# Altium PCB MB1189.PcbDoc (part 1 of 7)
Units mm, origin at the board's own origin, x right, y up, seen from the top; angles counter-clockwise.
Board outline 60.03 x 127.03 mm, 6 copper layers (TOP, L2_GND, L3_VCC, L4_SIG, L5_GND, BOTTOM), stack 1.58 mm thick; 273 components, 264 nets, 1114 pads, 811 vias.
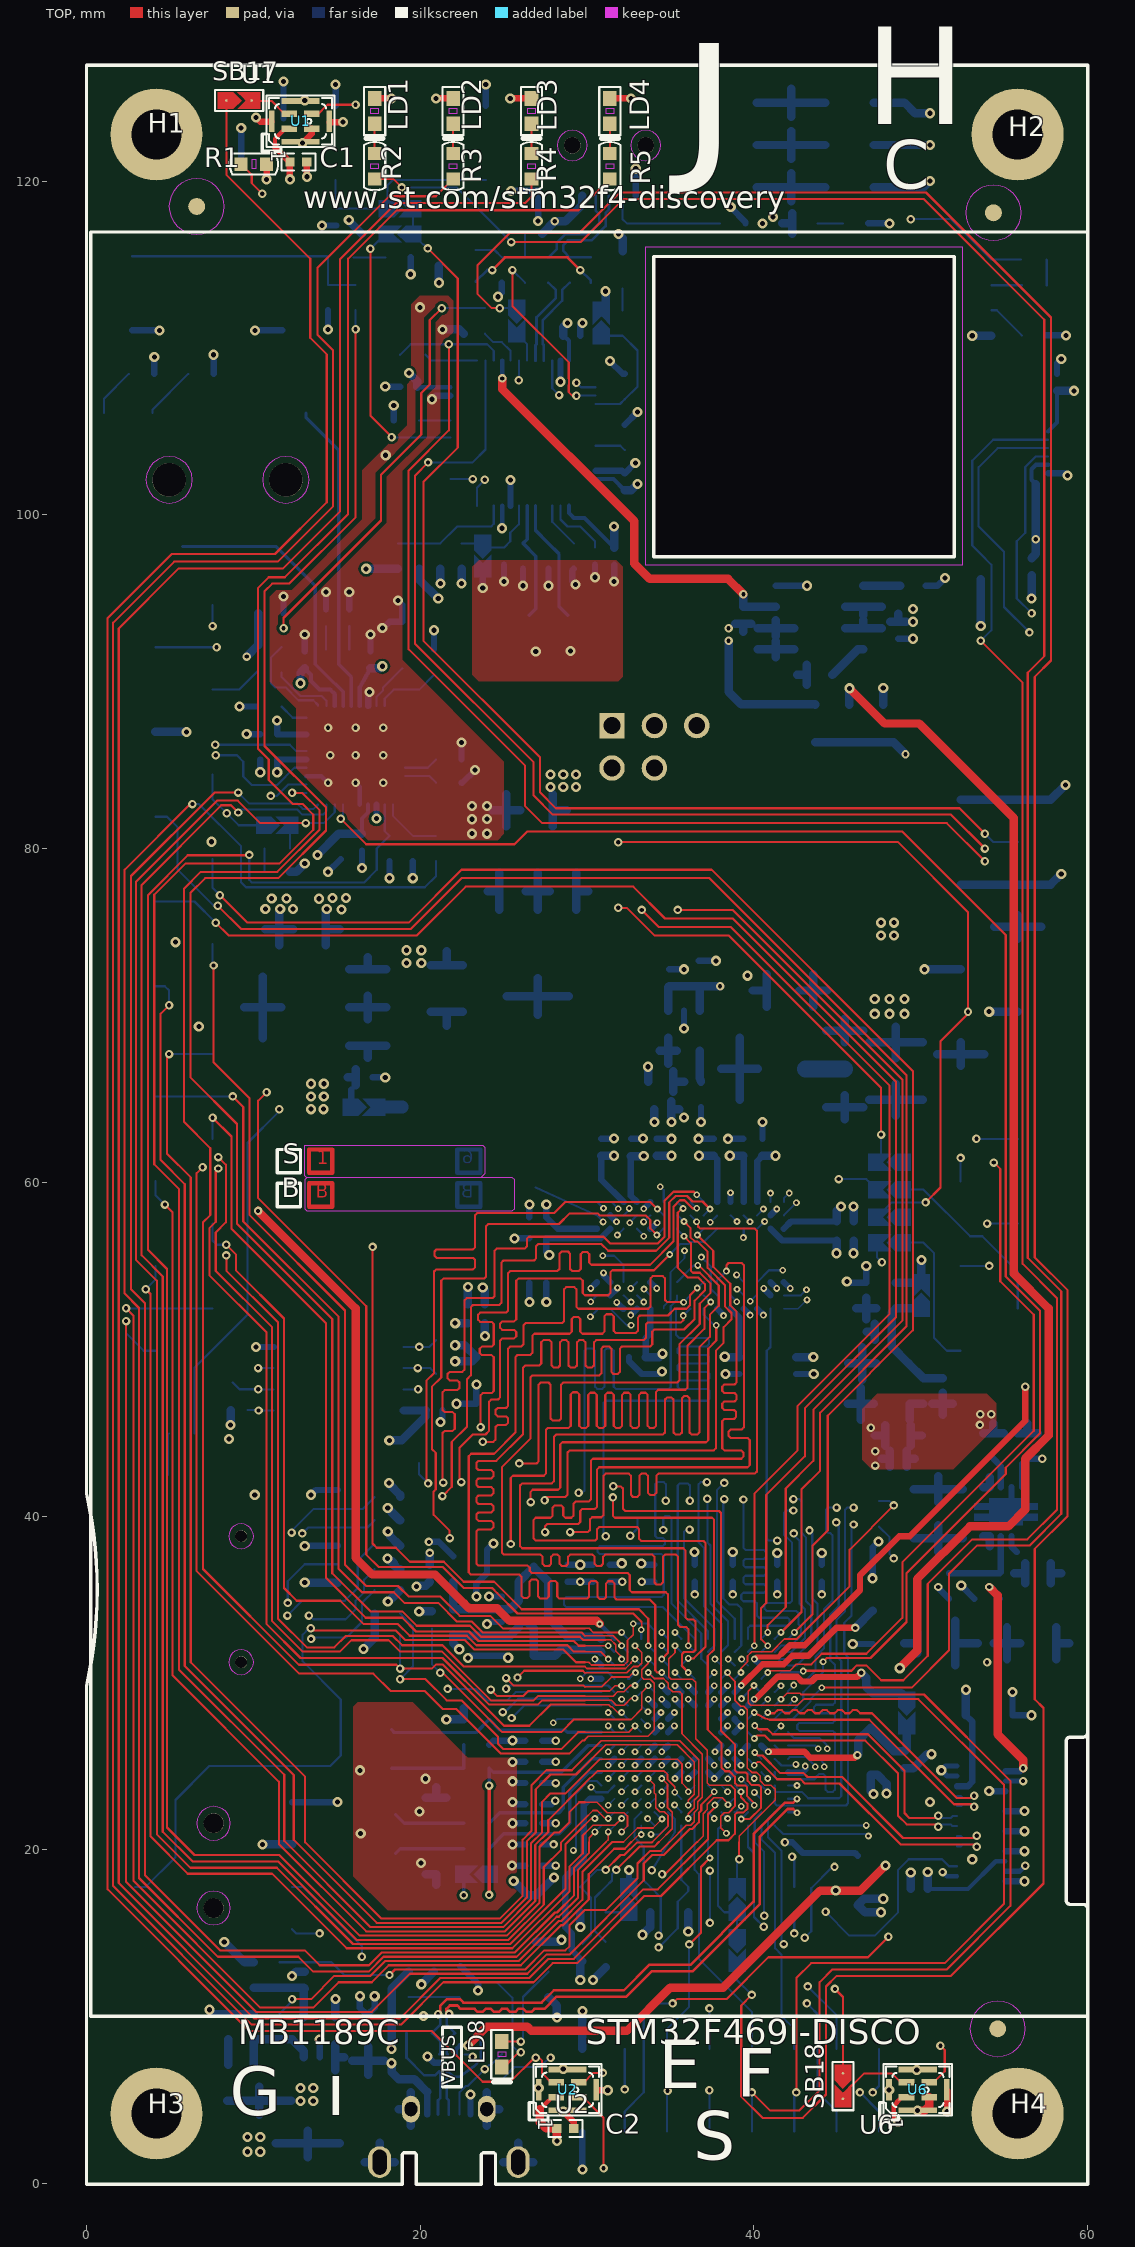
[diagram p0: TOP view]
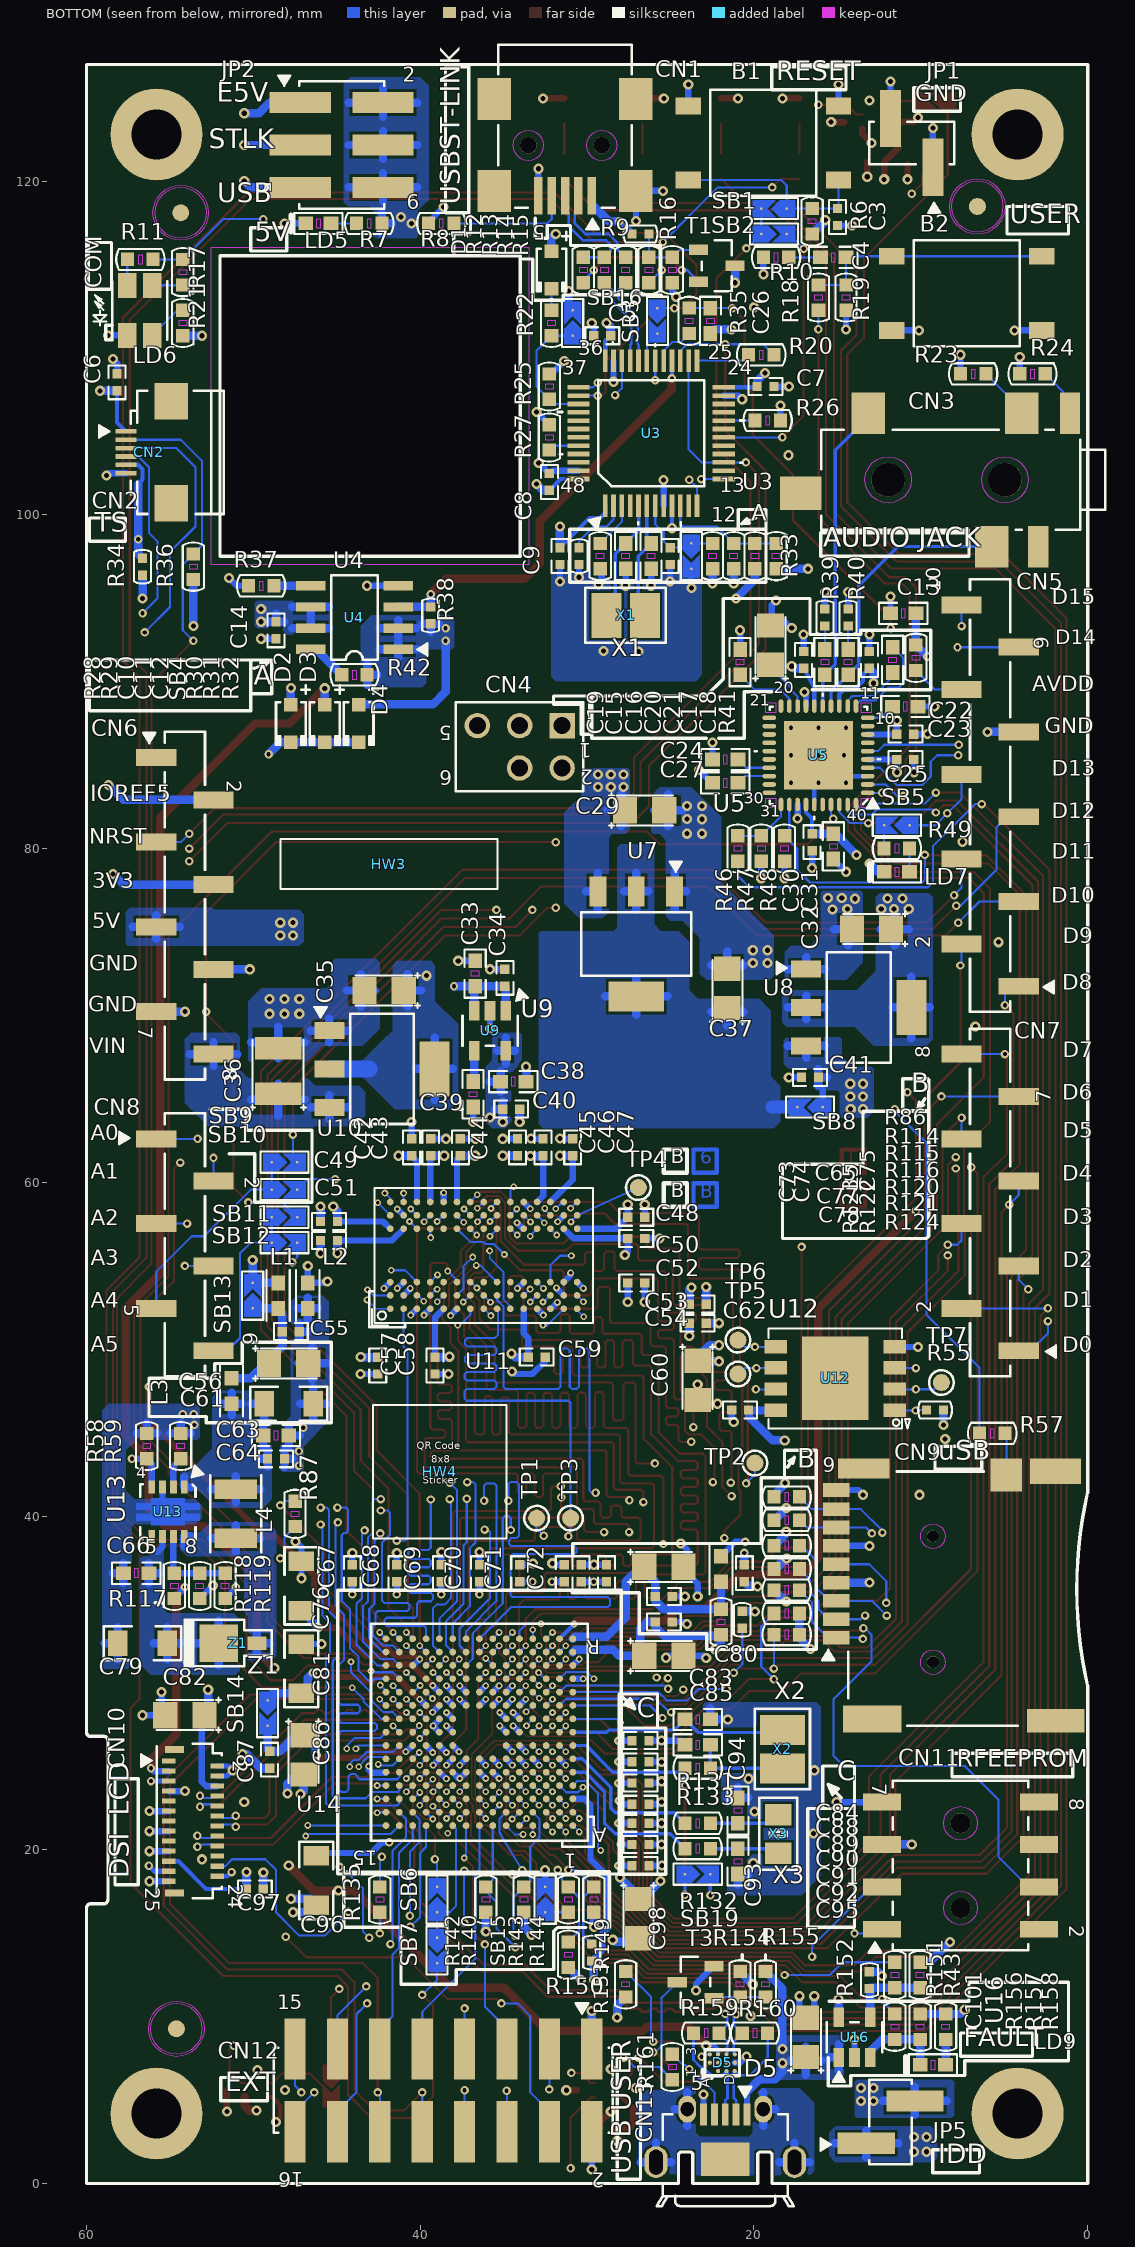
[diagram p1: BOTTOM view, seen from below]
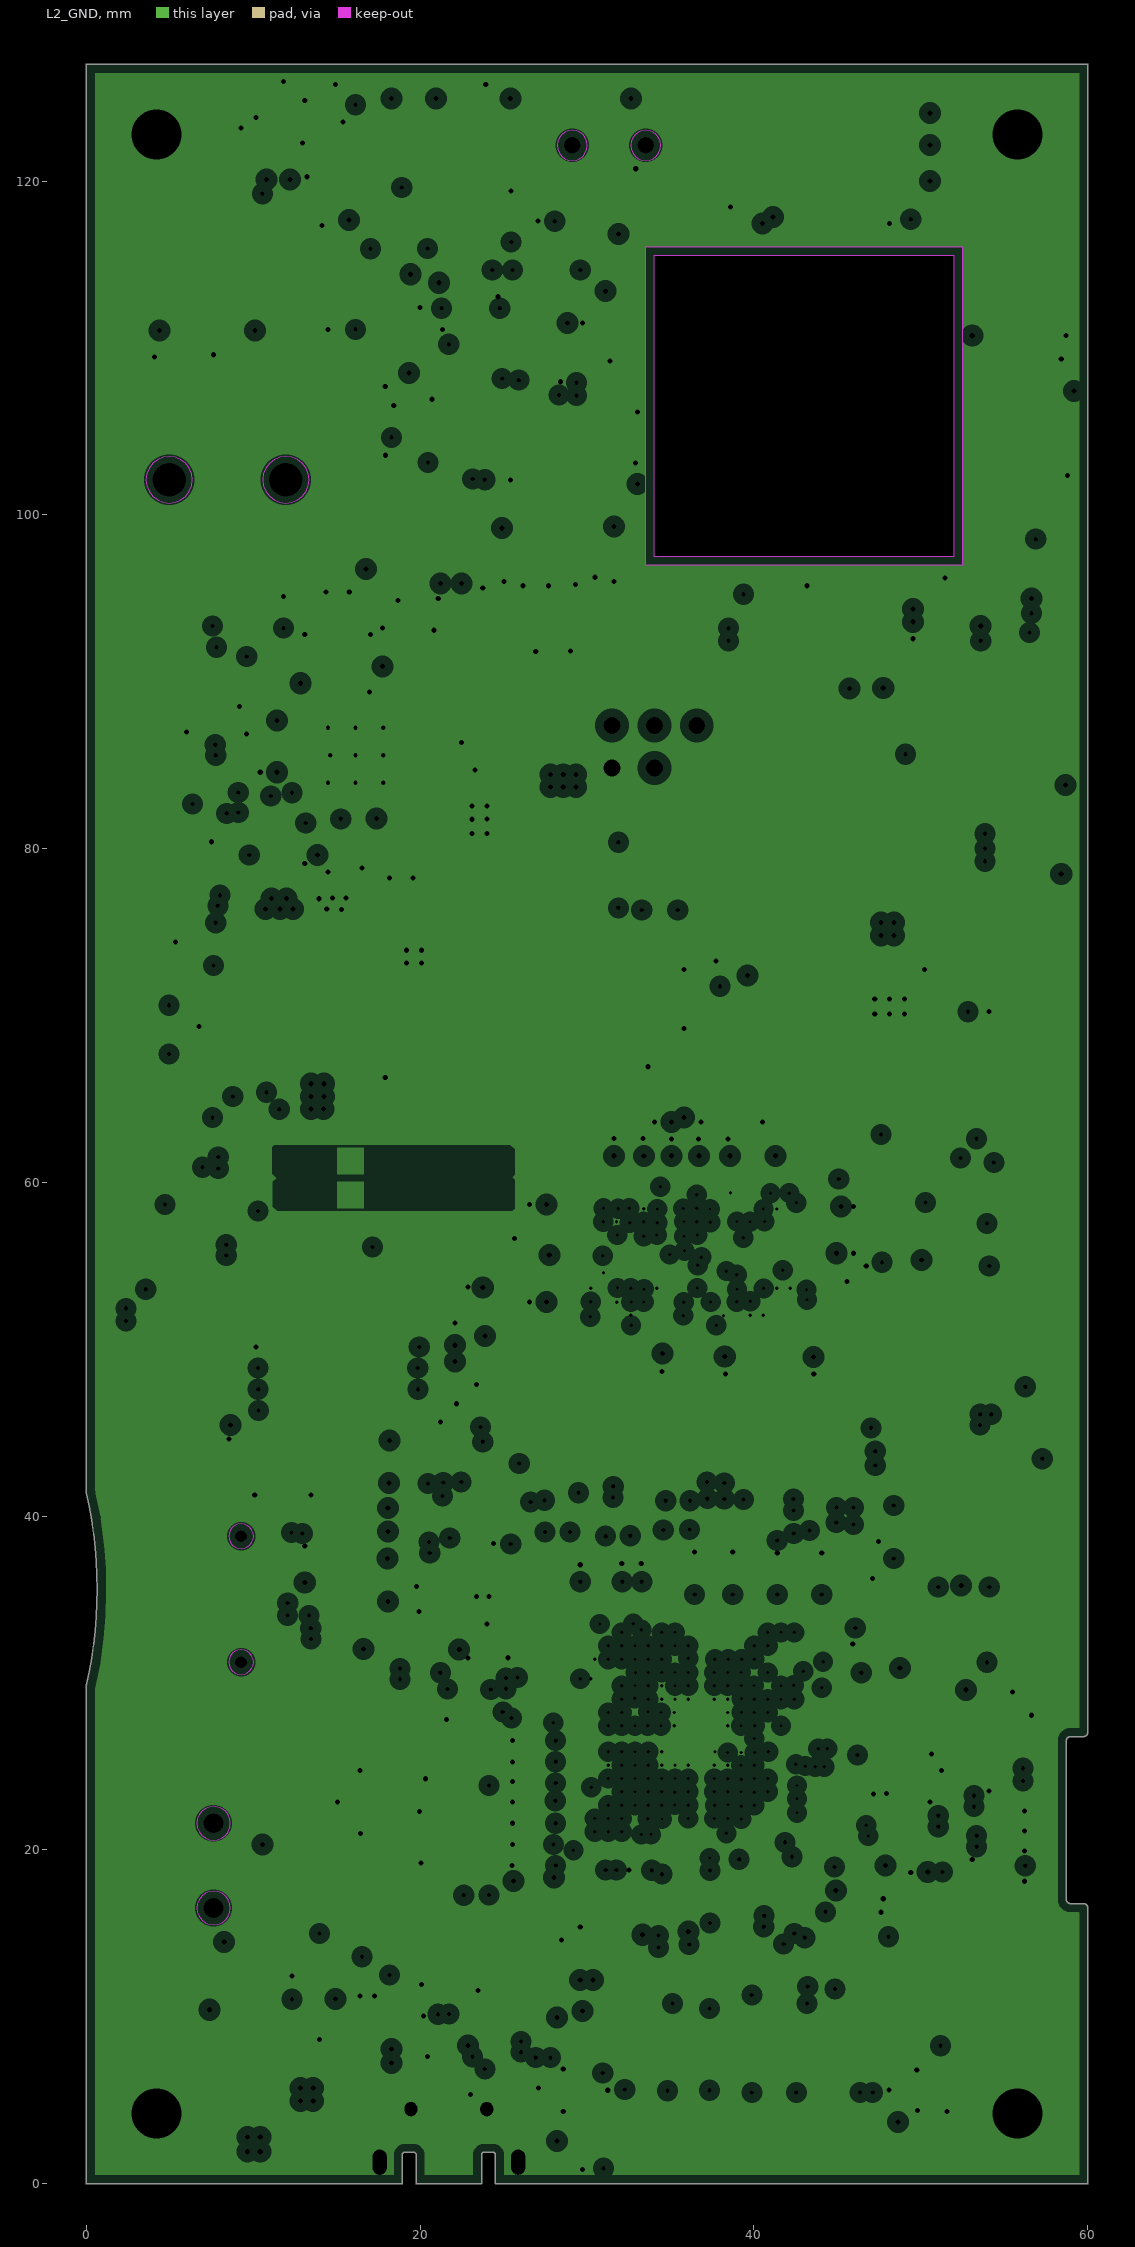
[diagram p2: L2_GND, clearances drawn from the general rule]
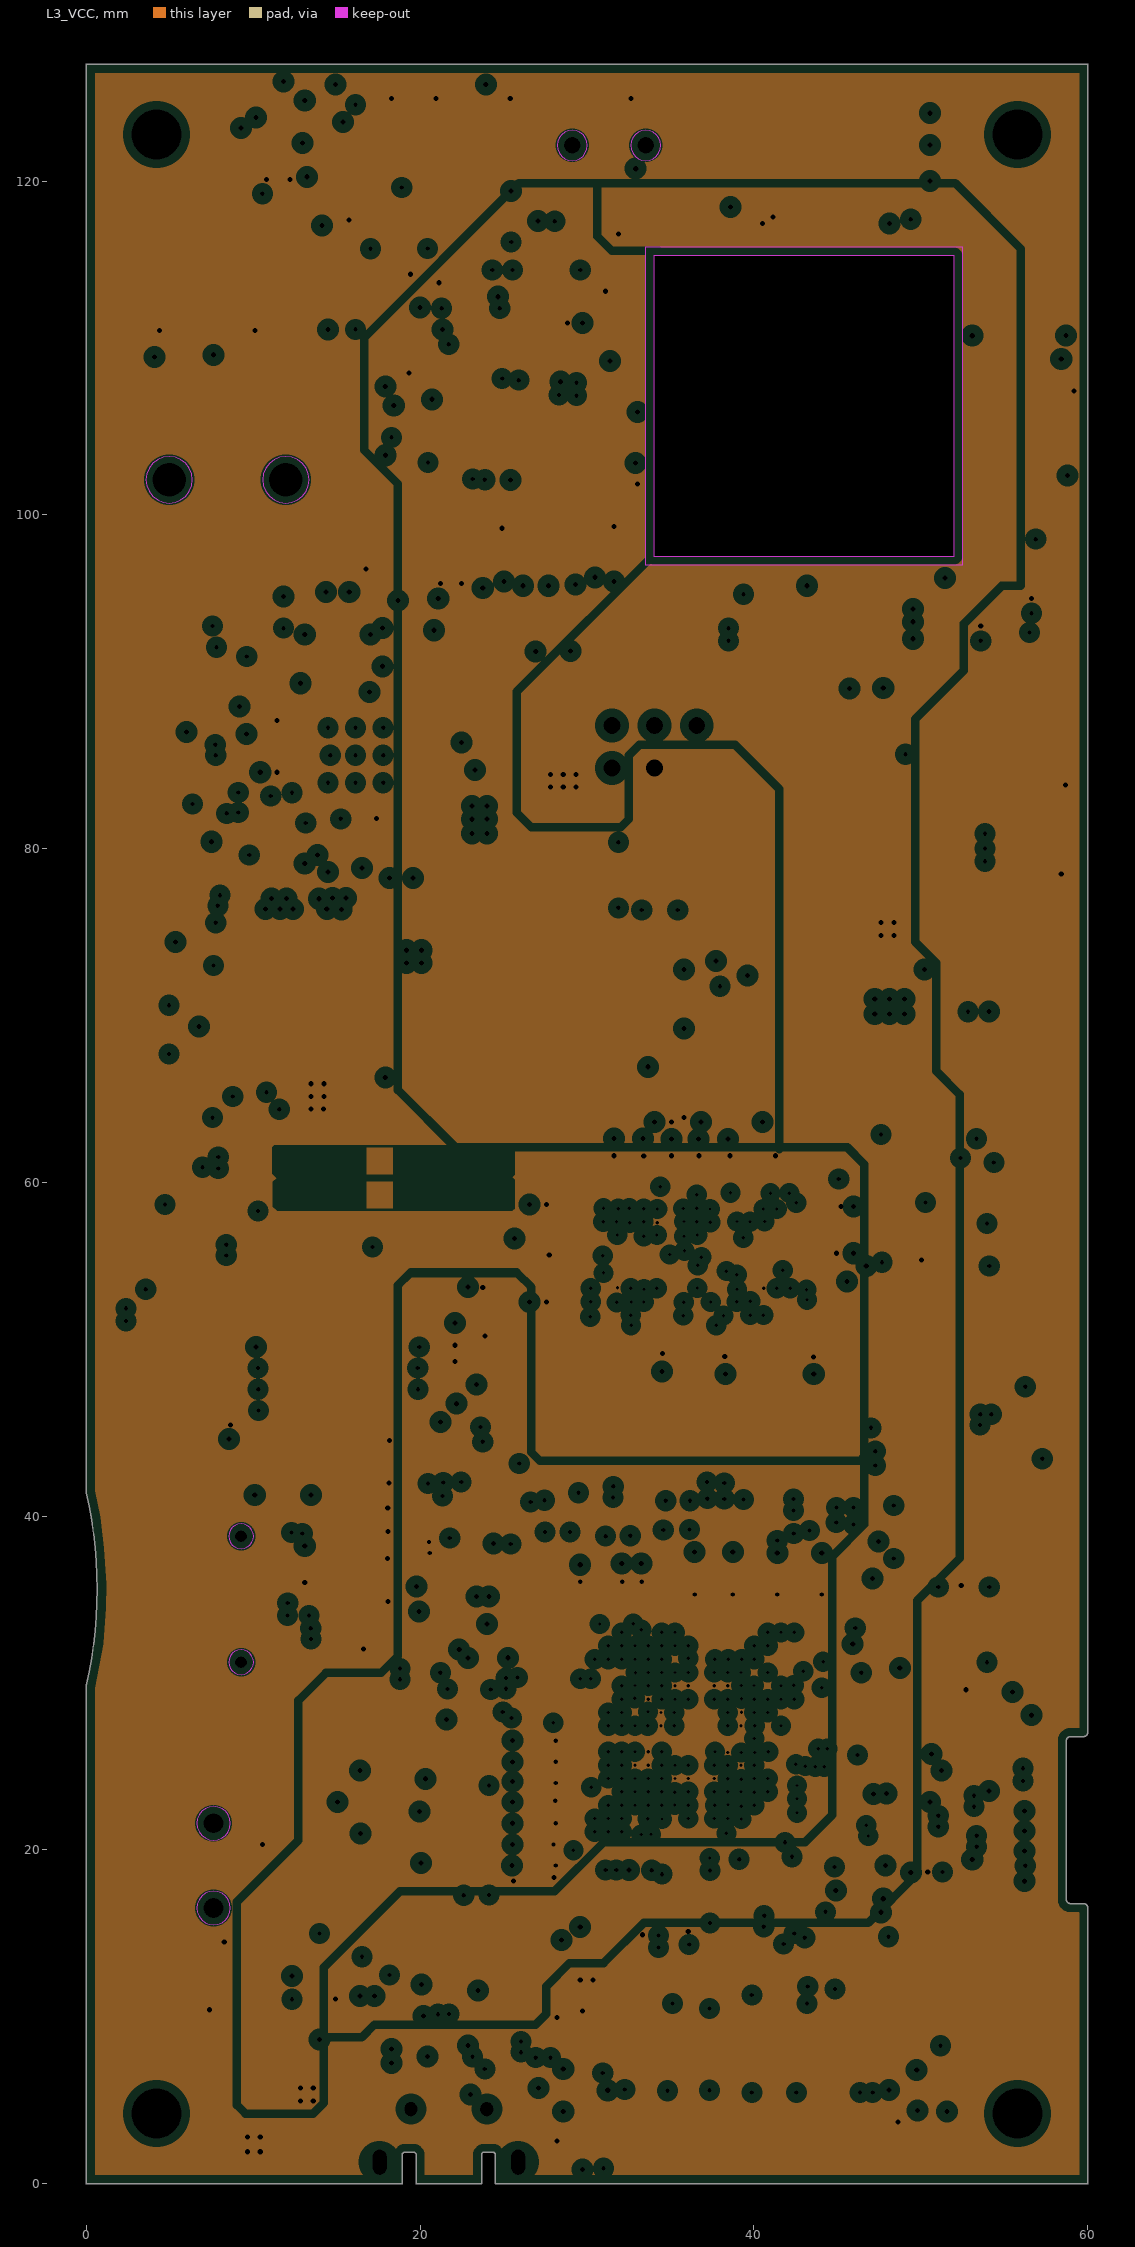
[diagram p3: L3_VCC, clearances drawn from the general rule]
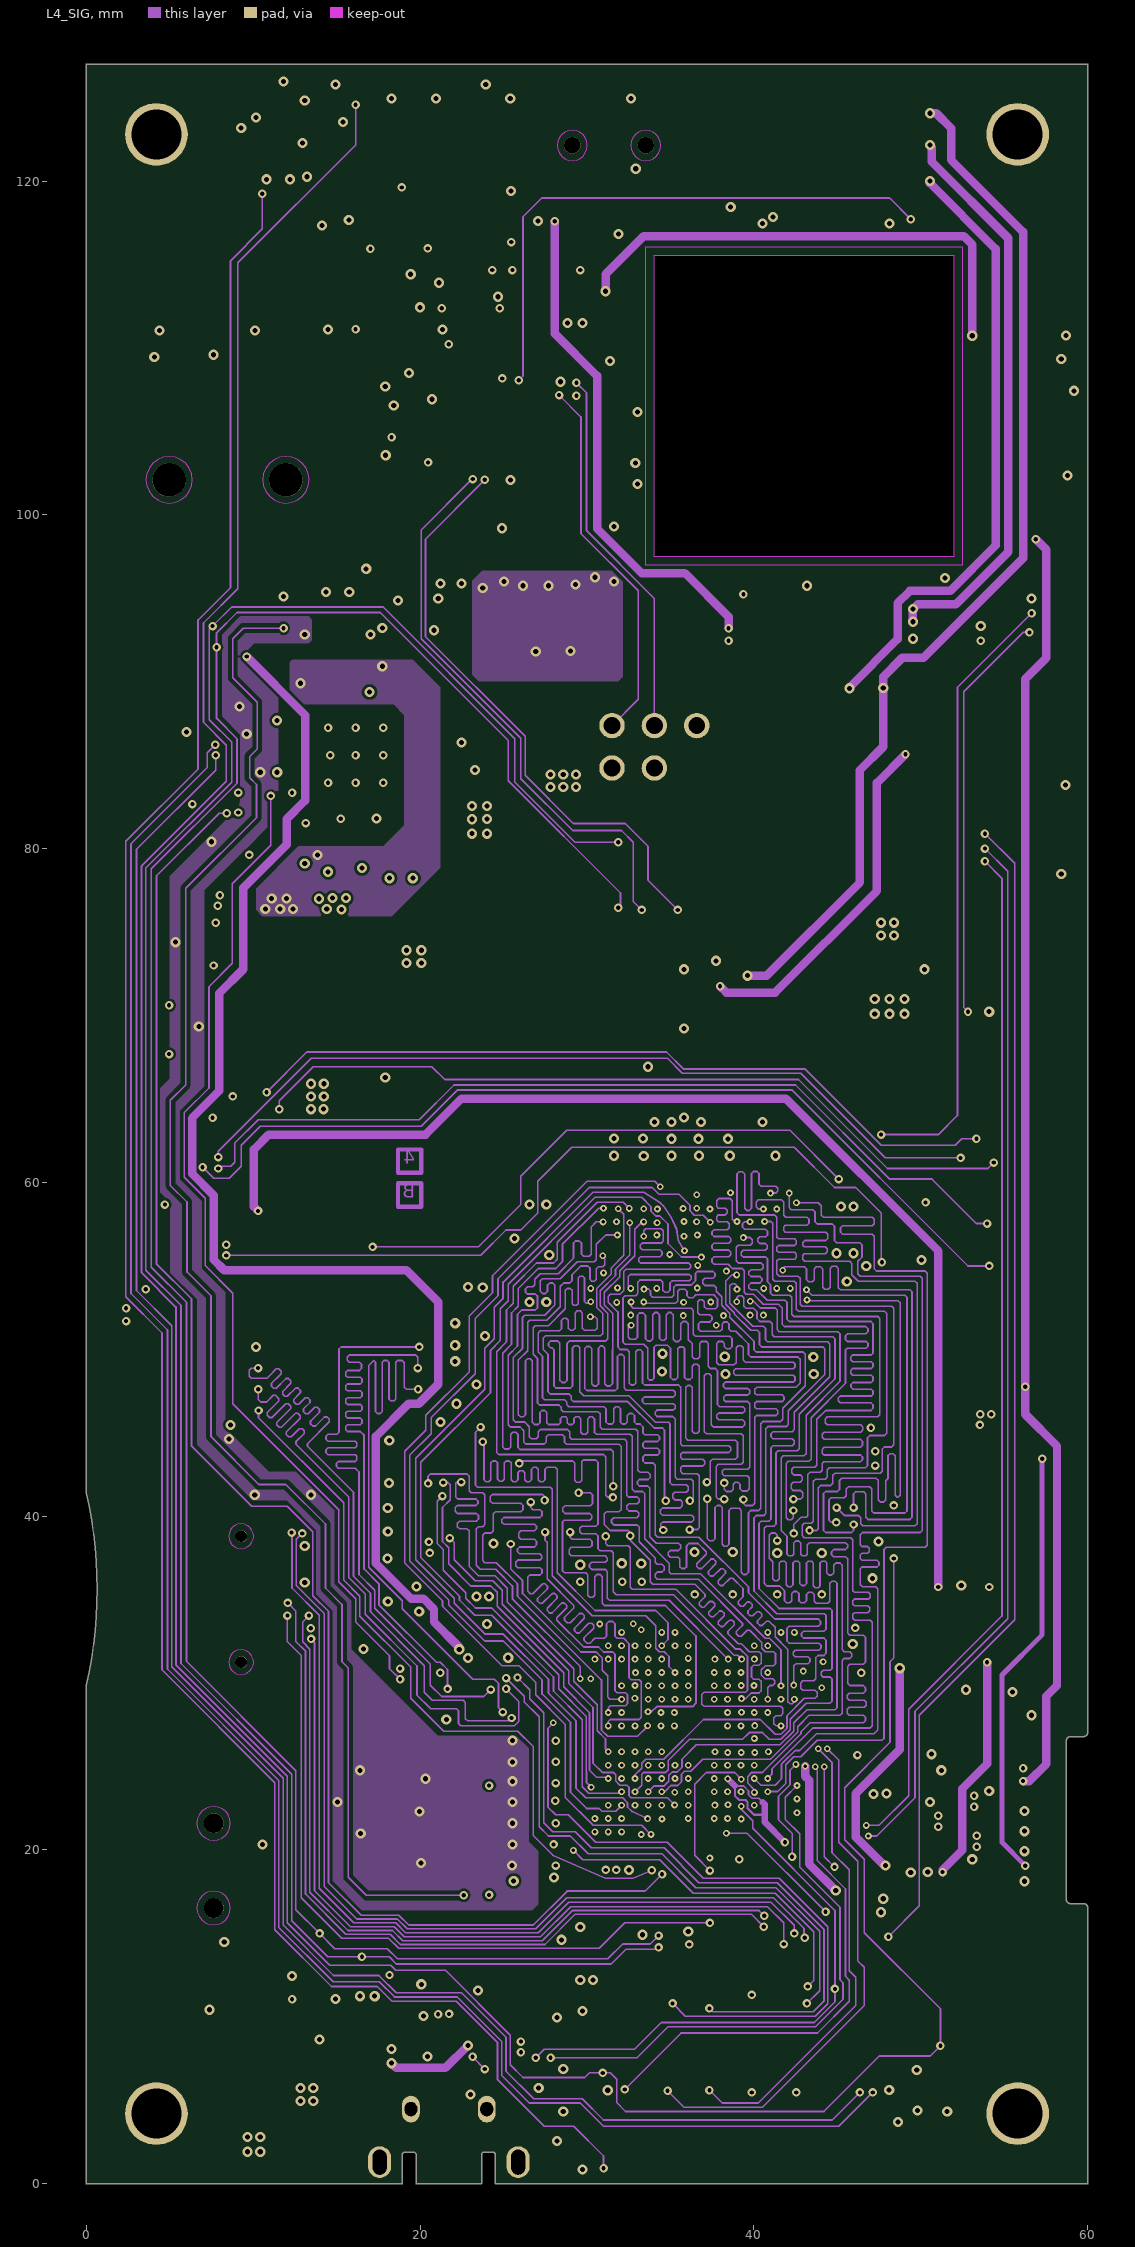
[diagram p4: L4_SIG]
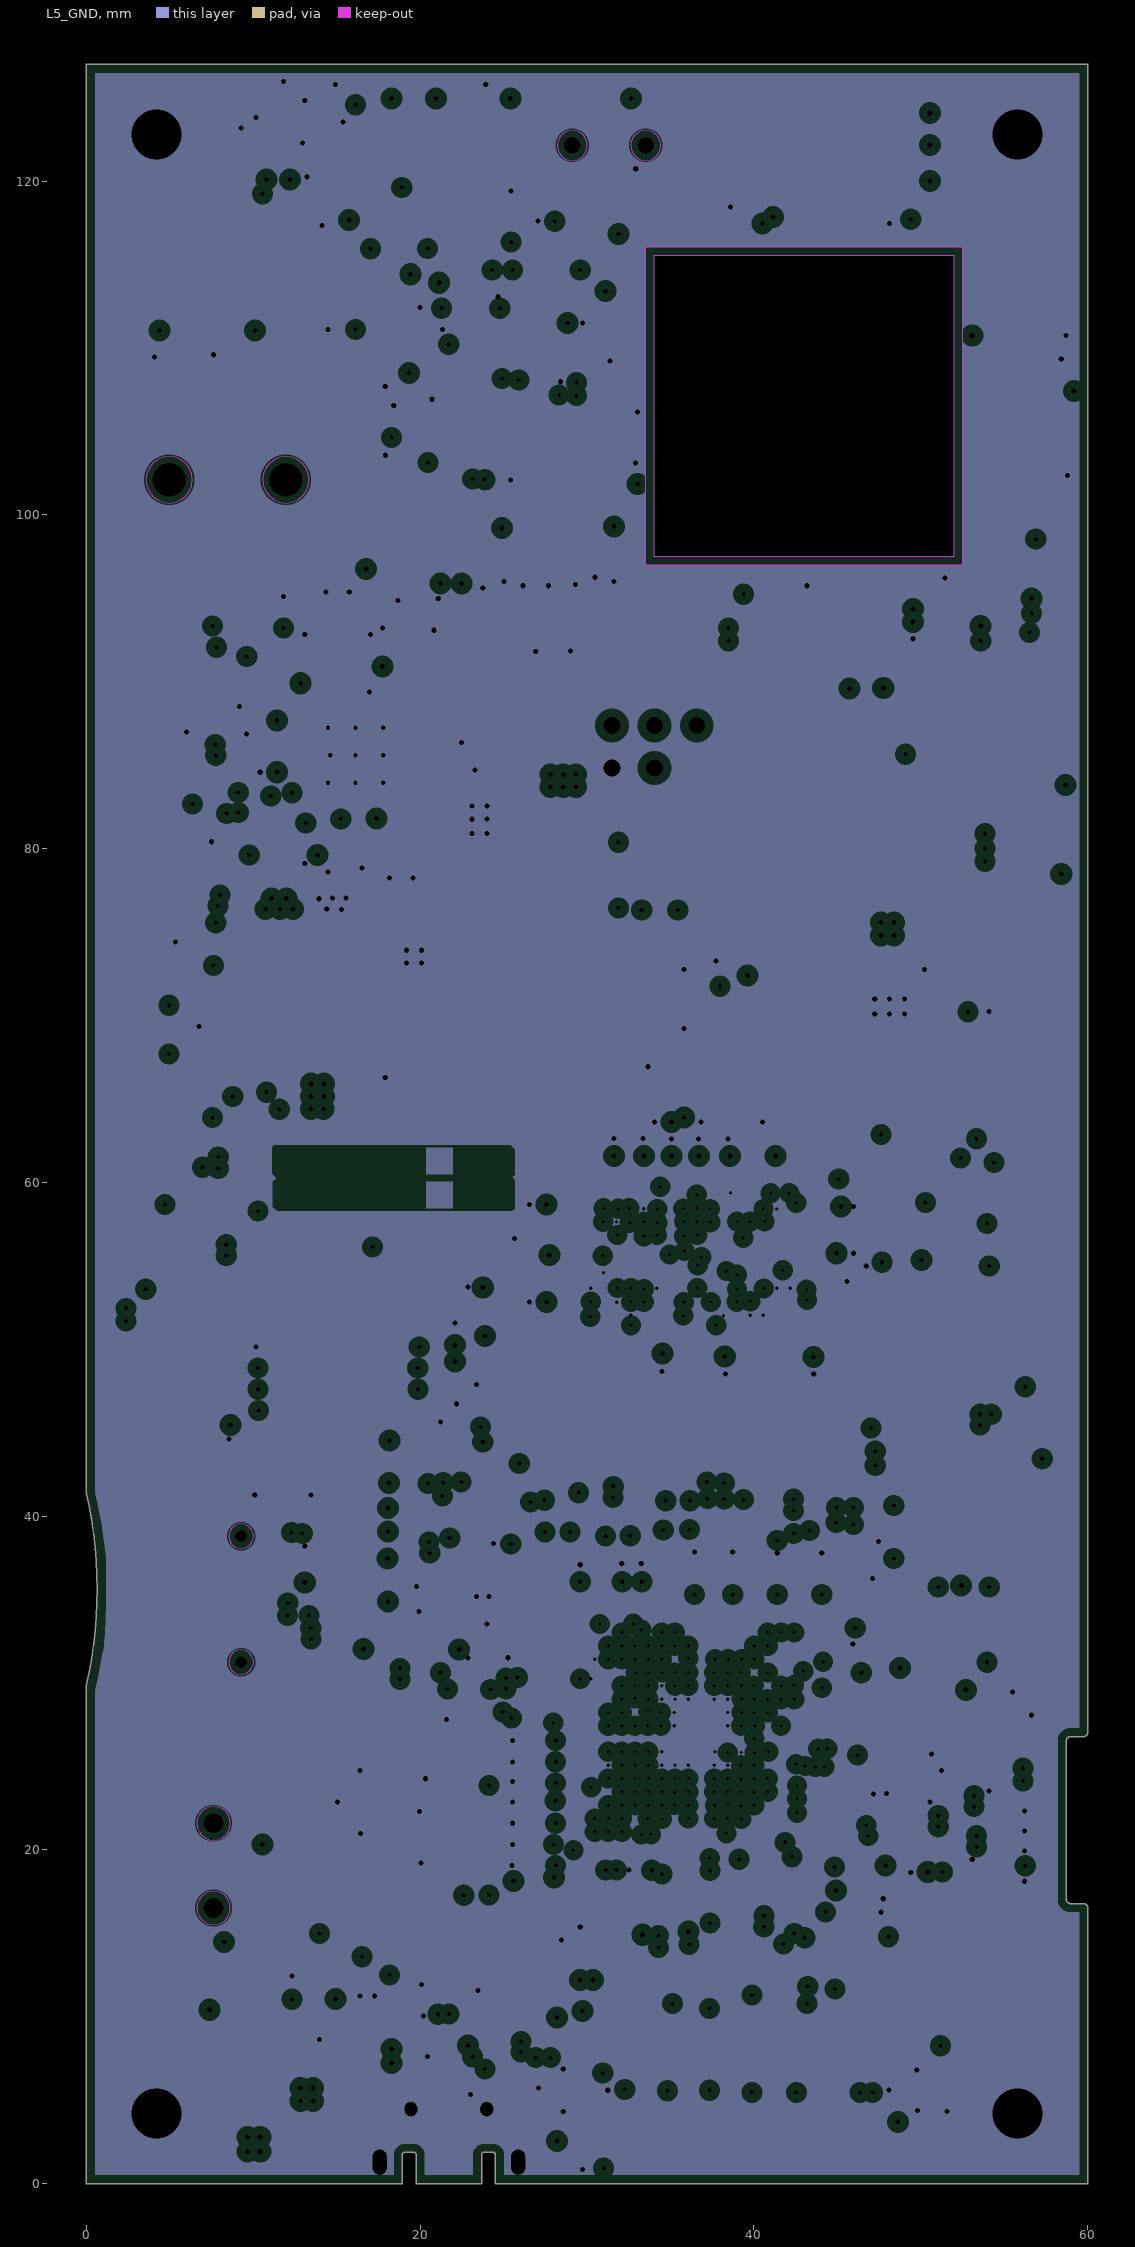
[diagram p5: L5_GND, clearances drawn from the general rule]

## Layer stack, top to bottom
Top Solder: solder mask 0.0102, Solder Resist, Dk 3.5
TOP: signal copper 0.0457
Dielectric 1: core 0.0991, FR-4, Dk 4.3
L2_GND: plane copper 0.0305, net GND
Dielectric2: core 0.1016, FR-4, Dk 4.3
L3_VCC: plane copper 0.0305, net +3V3
Dielectric3: core 0.9652, FR-4, Dk 4.3
L4_SIG: signal copper 0.0305
Dielectric4: core 0.1016, FR-4, Dk 4.3
L5_GND: plane copper 0.0305, net GND
Dielectric5: core 0.0991, FR-4, Dk 4.3
BOTTOM: signal copper 0.0457
Bottom Solder: solder mask 0.0102, Solder Resist, Dk 3.5

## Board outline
0,-0.013 cw(c0,0) -0.013,0 -0.013,29.845 cw(c0,29.845) -0.012,29.849 ccw(c-25.59,35.623) 0.631,35.623 ccw(c-25.59,35.623) -0.012,41.398 cw(c0,41.402) -0.013,41.402 -0.013,127 cw(c0,127) 0,127.013 60,127.013 cw(c60,127) 60.013,127 60.013,27.051 cw(c59.746,27.051) 59.746,26.784 58.967,26.784 ccw(c58.967,26.543) 58.726,26.543 58.726,17.018 ccw(c58.967,17.018) 58.967,16.777 59.746,16.777 cw(c59.746,16.51) 60.013,16.51 60.013,0 cw(c60,0) 60,-0.013 24.517,-0.013 cw(c24.517,0) 24.504,0 24.504,1.78 24.412,1.872 23.772,1.872 23.68,1.78 23.68,0 cw(c23.667,0) 23.667,-0.013 19.767,-0.013 cw(c19.767,0) 19.754,0 19.754,1.78 19.662,1.872 19.022,1.872 18.93,1.78 18.93,0 cw(c18.917,0) 18.917,-0.013
cut-out: 52,97.536 52,115.536 34,115.536 34,97.536

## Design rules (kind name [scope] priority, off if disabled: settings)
Clearance Clearance_Keepout [IsKeepout] p1: gap=0 ignorepadtopadclearanceinfootprint=FALSE
Clearance Clearance_STLK_MCO [(InNet('STLK_MCO') And (Layer = 'L4_SIG')) or (IsVia and Innet('PH0', 'VDD_MCU')) vs InPolygon and (Layer = 'L4_SIG')] p2: gap=0.254 ignorepadtopadclearanceinfootprint=FALSE except(0.153: Via-Fill Via-Poly Via-Region)
Clearance Clearance_BGA [TouchesRoom('RoomDefinition_U11','RoomDefinition_U14')] p3: gap=0.127 ignorepadtopadclearanceinfootprint=FALSE except(0.102: Arc-Arc Arc-Track Arc-SMDPad Arc-THPad Arc-Via Arc-Text Arc-Hole Track-Track Track-SMDPad Track-THPad Track-Via Track-Text Track-Hole SMDPad-Via SMDPad-Text SMDPad-Hole THPad-Via THPad-Text THPad-Hole Via-Text Via-Hole Text-Text Text-Hole; 0.381: Fill-Fill Fill-Poly Fill-Region Poly-Poly Poly-Region Region-Region)
Clearance Clearance_SB [HasFootprint('SB_0603') and IsRegion vs HasFootprint('SB_0603') and IsRegion] p4: gap=0.178 ignorepadtopadclearanceinfootprint=FALSE
Clearance Clearance_2W [InNetClass('A[0..15]') or InNetClass('DATA')] p5: gap=0.127 ignorepadtopadclearanceinfootprint=FALSE except(0.152: SMDPad-Fill SMDPad-Poly SMDPad-Region THPad-Fill THPad-Poly THPad-Region Via-Fill Via-Poly Via-Region Fill-Text Fill-Hole Poly-Text Poly-Hole Region-Text Region-Hole; 0.254: Arc-Fill Arc-Poly Arc-Region Track-Fill Track-Poly Track-Region; 0.508: Fill-Fill Fill-Poly Fill-Region Poly-Poly Poly-Region Region-Region)
Clearance [All] p6: gap=0.127 ignorepadtopadclearanceinfootprint=FALSE except(0.152: Arc-Fill Arc-Poly Arc-Region Track-Fill Track-Poly Track-Region SMDPad-Fill SMDPad-Poly SMDPad-Region THPad-Fill THPad-Poly THPad-Region Via-Fill Via-Poly Via-Region Fill-Text Fill-Hole Poly-Text Poly-Hole Region-Text Region-Hole; 0.508: Fill-Fill Fill-Poly Fill-Region Poly-Poly Poly-Region Region-Region)
DiffPairsRouting DiffPairsRouting_100Ohm [InDifferentialPair('HSSI_CLK', 'HSSI_D0', 'HSSI_D1')] p1: maxlimit=0.279 minlimit=0.102 mostfreqgap=0.277 toplayer_maxgap=0.254 toplayer_prefgap=0.252 toplayer_minwidth=0.127 toplayer_maxwidth=0.254 toplayer_prefwidth=0.129 midlayer1_minwidth=0.102 midlayer1_maxwidth=0.279 midlayer1_prefwidth=0.104 bottomlayer_maxgap=0.254 bottomlayer_prefgap=0.252 bottomlayer_minwidth=0.127 bottomlayer_maxwidth=0.254 bottomlayer_prefwidth=0.129 maxuncoupledlength=12.7
DiffPairsRouting DiffPairsRouting_90Ohm [InDifferentialPair('USB_FS1', 'MICROAB')] p2: maxlimit=0.254 minlimit=0.102 mostfreqgap=0.252 toplayer_maxgap=0.229 toplayer_prefgap=0.226 toplayer_minwidth=0.102 toplayer_maxwidth=0.155 toplayer_prefwidth=0.155 midlayer1_minwidth=0.102 midlayer1_maxwidth=0.13 midlayer1_prefwidth=0.13 bottomlayer_maxgap=0.229 bottomlayer_prefgap=0.226 bottomlayer_minwidth=0.102 bottomlayer_maxwidth=0.155 bottomlayer_prefwidth=0.155 maxuncoupledlength=12.7
HoleSize [All] p1: absolutevalues=TRUE maxlimit=3.048 minlimit=0.025 maxpercent=80.000 minpercent=20.000
MatchedLengths "Schematic Matched Net Lengths_20" [InNetClass('A[0..15]')] p1: tolerance=6.35 checknetsindiffpair=FALSE checkdiffpairvsdiffpair=TRUE checkxsignals=TRUE checkothers=TRUE
MatchedLengths "Schematic Matched Net Lengths_19" [InNet('PC0')] p2: tolerance=6.35 checknetsindiffpair=FALSE checkdiffpairvsdiffpair=TRUE checkxsignals=TRUE checkothers=TRUE
MatchedLengths "Schematic Matched Net Lengths_18" [InNetClass('D[0..31]')] p3: tolerance=6.35 checknetsindiffpair=FALSE checkdiffpairvsdiffpair=TRUE checkxsignals=TRUE checkothers=TRUE
MatchedLengths "Schematic Matched Net Lengths_16" [InNetClass('A[0..11]')] p4: tolerance=6.35 checknetsindiffpair=FALSE checkdiffpairvsdiffpair=TRUE checkxsignals=TRUE checkothers=TRUE
MatchedLengths "Schematic Matched Net Lengths_15" [InNet('PG8')] p5: tolerance=6.35 checknetsindiffpair=FALSE checkdiffpairvsdiffpair=TRUE checkxsignals=TRUE checkothers=TRUE
MatchedLengths "Schematic Matched Net Lengths_14" [InNet('PG15')] p6: tolerance=6.35 checknetsindiffpair=FALSE checkdiffpairvsdiffpair=TRUE checkxsignals=TRUE checkothers=TRUE
MatchedLengths "Schematic Matched Net Lengths_13" [InNet('PH3')] p7: tolerance=6.35 checknetsindiffpair=FALSE checkdiffpairvsdiffpair=TRUE checkxsignals=TRUE checkothers=TRUE
MatchedLengths "Schematic Matched Net Lengths_12" [InNet('PF11')] p8: tolerance=6.35 checknetsindiffpair=FALSE checkdiffpairvsdiffpair=TRUE checkxsignals=TRUE checkothers=TRUE
MatchedLengths "Schematic Matched Net Lengths_11" [InNet('HSSI_CLK_N')] p9: tolerance=2.54 checknetsindiffpair=TRUE checkdiffpairvsdiffpair=FALSE checkxsignals=FALSE checkothers=FALSE
MatchedLengths "Schematic Matched Net Lengths_10" [InNet('HSSI_CLK_P')] p10: tolerance=2.54 checknetsindiffpair=TRUE checkdiffpairvsdiffpair=FALSE checkxsignals=FALSE checkothers=FALSE
MatchedLengths "Schematic Matched Net Lengths_9" [InNet('HSSI_D0_N')] p11: tolerance=2.54 checknetsindiffpair=TRUE checkdiffpairvsdiffpair=FALSE checkxsignals=FALSE checkothers=FALSE
MatchedLengths "Schematic Matched Net Lengths_8" [InNet('HSSI_D0_P')] p12: tolerance=2.54 checknetsindiffpair=TRUE checkdiffpairvsdiffpair=FALSE checkxsignals=FALSE checkothers=FALSE
MatchedLengths "Schematic Matched Net Lengths_7" [InNet('HSSI_D1_N')] p13: tolerance=2.54 checknetsindiffpair=TRUE checkdiffpairvsdiffpair=FALSE checkxsignals=FALSE checkothers=FALSE
MatchedLengths "Schematic Matched Net Lengths_6" [InNet('PF8')] p14: tolerance=2.54 checknetsindiffpair=FALSE checkdiffpairvsdiffpair=TRUE checkxsignals=TRUE checkothers=TRUE
MatchedLengths "Schematic Matched Net Lengths_5" [InNet('PF9')] p15: tolerance=2.54 checknetsindiffpair=FALSE checkdiffpairvsdiffpair=TRUE checkxsignals=TRUE checkothers=TRUE
MatchedLengths "Schematic Matched Net Lengths_4" [InNet('PF7')] p16: tolerance=2.54 checknetsindiffpair=FALSE checkdiffpairvsdiffpair=TRUE checkxsignals=TRUE checkothers=TRUE
MatchedLengths "Schematic Matched Net Lengths_3" [InNet('PF6')] p17: tolerance=2.54 checknetsindiffpair=FALSE checkdiffpairvsdiffpair=TRUE checkxsignals=TRUE checkothers=TRUE
MatchedLengths "Schematic Matched Net Lengths_2" [InNet('PB6')] p18: tolerance=2.54 checknetsindiffpair=FALSE checkdiffpairvsdiffpair=TRUE checkxsignals=TRUE checkothers=TRUE
MatchedLengths "Schematic Matched Net Lengths_1" [InNet('PF10')] p19: tolerance=2.54 checknetsindiffpair=FALSE checkdiffpairvsdiffpair=TRUE checkxsignals=TRUE checkothers=TRUE
MatchedLengths "Schematic Matched Net Lengths" [InNet('HSSI_D1_P')] p20: tolerance=2.54 checknetsindiffpair=TRUE checkdiffpairvsdiffpair=FALSE checkxsignals=FALSE checkothers=FALSE
PlaneClearance PlaneClearance_Fixations [HasFootprint('HOLE_C5R5D3')] p1: clearance=0.381
PlaneClearance "PlaneClearance_Via 16mil" [(ObjectKind = 'Via') And (AsMils(PadXSize_TopLayer) = 16) And (AsMils(PadXSize_MidLayer1) = 16) And (AsMils(PadXSize_BottomLayer) = 16)] p2: clearance=0.229
PlaneClearance PlaneClearance_CN4 [InComponent('CN4')] p3: clearance=0.381
PlaneClearance PlaneClearance_NonPlatedPads [(PadIsPlated = 'False')] p4: clearance=0.406
PlaneClearance PlaneClearance_Via [IsVia] p5: clearance=0.254
PlaneClearance [All] p6: clearance=0.508
PlaneConnect PlaneConnect_Fixations [HasFootprint('HOLE_C5R5D3')] p1: planeconnectstyle=Relief reliefexpansion=0.203 reliefentries=4 reliefconductorwidth=0.762 reliefairgap=0.178
PlaneConnect [All] p2: pad.planeconnectstyle=Relief pad.reliefexpansion=0.203 pad.reliefentries=4 pad.reliefconductorwidth=0.381 pad.reliefairgap=0.178 via.planeconnectstyle=Direct via.reliefexpansion=0.508 via.reliefentries=4 via.reliefconductorwidth=0.254 via.reliefairgap=0.254
PolygonConnect PolygonConnect_CN13 [IsPad and (Name = 'CN13-10')] p1: connectstyle=Direct reliefconductorwidth=0.254 reliefentries=4 polygonreliefangle="90 Angle" airgapwidth=0.254
PolygonConnect [All] p2: thpad.connectstyle=Relief thpad.reliefconductorwidth=0.254 thpad.reliefentries=4 thpad.polygonreliefangle="90 Angle" thpad.airgapwidth=0.152 smdpad.connectstyle=Relief smdpad.reliefconductorwidth=0.254 smdpad.reliefentries=4 smdpad.polygonreliefangle="90 Angle" smdpad.airgapwidth=0.152 via.connectstyle=Direct via.reliefconductorwidth=0.254 via.reliefentries=4 via.polygonreliefangle="90 Angle" via.airgapwidth=0.254
RoomDefinition RoomDefinition_U11 [False] p1: confinementstyle=ConfineIn formatcopy=TRUE lockcomponents=FALSE outline 29.21,59.95 43.155,59.95 43.155,51.13 29.21,51.13
RoomDefinition RoomDefinition_U14 [False] p2: confinementstyle=ConfineIn formatcopy=TRUE lockcomponents=FALSE outline 29.87,33.63 43.028,33.63 43.028,20.472 29.87,20.472
RoutingVias [All] p1: holewidth=0.3 width=0.6 viastyle="Through Hole" minholewidth=0.2 minwidth=0.25 maxholewidth=0.5 maxwidth=0.65
SolderMaskExpansion SolderMaskExpansion_1 [IsVia] p1: expansion=0.076 istentingtop=FALSE soldermaskfromhole=TRUE
SolderMaskExpansion [All] p2: expansion=0.076 istentingtop=FALSE
Width Width_BGA [TouchesRoom('RoomDefinition_U11','RoomDefinition_U14')] p1: maxlimit=1.016 minlimit=0.102 preferedwidth=0.102
Width Width_20mil [InNet('GND', 'E5V', '+1V8', '+3V3', 'VDD_MCU', 'U5V_ST_LINK')] p2: maxlimit=2.032 minlimit=0.127 preferedwidth=0.508
Width [All] p3: maxlimit=1.016 minlimit=0.102 preferedwidth=0.127 toplayer_minwidth=0.127 midlayer1_prefwidth=0.102 bottomlayer_minwidth=0.127 minimp=2.670000 maximp=36.460000 favimp=1.510000
26 further rules are at their usual default settings.

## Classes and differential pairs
net class D[0..31]: D0 D1 D2 D3 D4 D5 D6 D7 D8 D9 D10 D11 D12 D13 D14 D15 D16 D17 D18 D19 D20 D21 D22 D23 D24 D25 D26 D27 D28 D29 D30 D31
net class A[0..15]: A0 A1 A2 A3 A4 A5 A6 A7 A8 A9 A10 A11 A14 A15
component class U_USB_OTG_FS: C101 CN13 D5 LD8 LD9 R43 R151 R152 R153 R154 R155 R156 R157 R158 R159 R160 R161 T3 U16
component class U_ST_LINK_V2-1: C5 C7 C8 C9 C10 C11 C12 C14 C26 C33 C34 C38 C39 C40 CN1 CN4 D1 D2 D3 D4 LD6 R8 R9 R11 R12 R13 R14 R15 R16 R17 R20 R21 R22 R25 R26 R27 R28 R29 R30 R31 R32 R33 R35 R37 R38 R42 SB2 SB3 SB4 SB16 T1 U3 U4 U9 X1
component class U_QSPI: C62 R55 TP5 TP6 TP7 U12
component class U_Power: C29 C32 C35 C36 C37 C41 JP1 JP2 JP5 LD5 R7 SB8 U7 U8 U10
component class U_Peripherals: B1 B2 C3 C4 CN9 CN11 LD1 LD2 LD3 LD4 R2 R3 R4 R5 R6 R10 R18 R19 R57 R86 R114 R115 R116 R120 SB1
component class U_Memory: C42 C43 C44 C45 C46 C47 C48 C49 C50 C51 C52 C57 C58 C59 TP2 TP3 TP4 U11
component class U_MCU: C53 C54 C60 C65 C67 C68 C69 C70 C71 C72 C73 C74 C75 C76 C77 C78 C80 C81 C83 C84 C85 C86 C87 C88 C89 C90 C91 C92 C93 C94 C95 C96 C98 L5 R87 R121 R122 R123 R124 R131 R132 R133 R135 R140 R142 R143 R144 R149 R150 SB6 SB7 SB14 SB15 SB19 TP1 U14 X2 X3
component class U_ExtensionConnector: CN12
component class U_DSI_LCD: C6 C55 C56 C61 C63 C64 C66 C79 C82 C97 CN2 CN10 L1 L2 L3 L4 R34 R36 R58 R59 R117 R118 R119 SB13 U13 Z1 ZZ1
component class U_AUDIO2: C1 C2 C15 C16 C17 C18 C19 C20 C21 C22 C23 C24 C25 C27 C30 C31 CN3 R1 R23 R24 R39 R40 R46 R47 R48 SB17 SB18 U1 U2 U5 U6
component class "U_Arduino_ Connectors": C13 CN5 CN6 CN7 CN8 LD7 R41 R49 SB5 SB9 SB10 SB11 SB12
component class U_Top: H1 H2 H3 H4 HW3 HW4 ZZ2 ZZ3 ZZ4 ZZ5 ZZ6 ZZ7 ZZ8 ZZ9
differential pair USB_FS1: +USB_FS1_P -USB_FS1_N
differential pair MICROAB: +MICROAB_P -MICROAB_N
differential pair HSSI_D1: +HSSI_D1_P -HSSI_D1_N
differential pair HSSI_D0: +HSSI_D0_P -HSSI_D0_N
differential pair HSSI_CLK: +HSSI_CLK_P -HSSI_CLK_N

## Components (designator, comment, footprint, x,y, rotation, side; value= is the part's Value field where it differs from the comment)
B1 "CTSM-644N-V-T/R" PB10 19.431,122.301 r0 bottom
B2 "CTSM-644B-V-T/R" PB10 7.239,113.284 r0 bottom
C1 "100nF" 0402C#1 12.7,121.158 r180 top
C2 "100nF" 0402C#1 28.702,3.302 r180 top
C3 "100nF" 0402C#1 14.986,117.856 r90 bottom value=100NF
C4 "[N/A]" 0603C#1 15.24,115.443 r0 bottom value=100pF
C5 "100nF" 0402C#2 29.083,110.744 r0 bottom
C6 "100nF" 0402C#1 58.166,107.95 r270 bottom
C7 "100nF" 0402C#1 19.304,107.696 r0 bottom
C8 "100nF" 0402C#1 32.258,101.981 r270 bottom
C9 "100nF" 0402C#1 31.623,97.536 r90 bottom
C10 "10pF" 0603C#2 27.686,97.536 r270 bottom
C11 "10pF" 0603C#2 26.162,97.536 r270 bottom
C12 "100nF" 0402C#1 25.019,97.536 r90 bottom
C13 "[N/A]" 0603C#1 11.049,94.107 r0 bottom value=10nF
C14 "100nF" 0402C#1 48.641,93.091 r90 bottom
C15 "10uF" CPOL_TAJ-A_1206_H180 19,92.2 r90 bottom value="10uF (16V)"
C16 "100nF" 0402C#1 17.018,91.313 r90 bottom
C17 "100nF" 0402C#1 13.081,91.313 r90 bottom value=100NF
C18 "1uF" 0603C#2 11.684,91.313 r270 bottom
C19 "1uF" 0603C#2 20.828,91.186 r270 bottom
C20 "22nF" 0603C#2 15.748,91.186 r90 bottom
C21 "22nF" 0603C#2 14.351,91.186 r90 bottom
C22 "1uF" 0603C#2 10.922,88.519 r0 bottom
C23 "100nF" 0402C#1 10.922,86.868 r0 bottom
C24 "150pF_NPO_5%_0603" 0603C#1 21.717,85.344 r0 bottom value=150pF
C25 "100nF" 0402C#2 10.922,85.344 r0 bottom
C26 "20pF" 0603C#2 22.606,111.633 r270 bottom
C27 "150pF_NPO_5%_0603" 0603C#1 21.717,83.947 r0 bottom value=150pF
C29 "10uF" CPOL_TAJ-A_1206_H180 26.543,82.296 r180 bottom value="10uF (16v)"
C30 "100nF" 0402C#1 16.51,80.391 r270 bottom
C31 "1uF" 0603C#2 15.24,80.137 r270 bottom
C32 "10uF" CPOL_TAJ-A_1206_H180 12.954,75.184 r0 bottom value="10uF (16V)"
C33 "1uF" 0603C#2 36.703,72.517 r270 bottom
C34 "100nF" 0402C#1 34.925,72.263 r270 bottom
C35 "10uF" CPOL_TAJ-A_1206_H180 42.164,71.501 r0 bottom value="10uF (16V)"
C36 "10uF(25V)" CPOL_TAJ-B_1210_H210 48.514,66.675 r90 bottom value="10uF (25V)"
C37 "10uF" CPOL_TAJ-A_1206_H180 21.59,71.628 r90 bottom value="10uF (16V)"
C38 "1uF" 0603C#1 34.417,66.04 r0 bottom
C39 "10nF" 0603C#2 36.83,65.278 r90 bottom value=10NF
C40 "100nF" 0402C#1 34.544,64.389 r0 bottom
C41 "100nF" 0402C#1 16.637,66.294 r0 bottom
C42 "100nF" 0402C#1 40.513,62.103 r90 bottom
C43 "100nF" 0402C#1 39.37,62.103 r90 bottom
C44 "100nF" 0402C#1 37.592,62.103 r90 bottom
C45 "100nF" 0402C#1 34.163,62.103 r90 bottom
C46 "100nF" 0402C#1 32.639,62.103 r90 bottom
C47 "100nF" 0402C#1 30.861,62.103 r90 bottom
C48 "100nF" 0402C#2 27.051,57.912 r0 bottom
C49 "100nF" 0402C#1 45.466,57.658 r0 bottom
C50 "100nF" 0402C#2 27.051,56.642 r0 bottom
C51 "100nF" 0402C#1 45.466,56.515 r0 bottom
C52 "100nF" 0402C#2 27.051,53.975 r0 bottom
C53 "100nF" 0402C#2 23.368,52.705 r0 bottom
C54 "100nF" 0402C#2 23.368,51.562 r0 bottom
C55 "100nF" 0402C#2 47.752,51.054 r0 bottom
C56 "10uF" CPOL_TAJ-A_1206_H180 47.879,49.149 r180 bottom value="10uF (16V)"
C57 "100nF" 0402C#1 42.545,49.022 r270 bottom
C58 "100nF" 0402C#1 39.116,49.022 r270 bottom
C59 "100nF" 0402C#2 33.02,49.53 r0 bottom
C60 "4.7uF" CPOL_TAJ-A_1206_H180 23.368,48.133 r270 bottom value="4.7uF 16V"
C61 "4.7uF/10V" 1206C#1 47.879,46.736 r0 bottom value=4.7uF
C62 "100nF" 0402C#1 20.828,46.355 r0 bottom
C63 "10nF" 0603C#2 48.641,44.831 r0 bottom
C64 "100nF" 0402C#1 48.641,43.434 r0 bottom
C65 "1uF" CPOL_TAJ-A_1206_H180 25.4,36.957 r180 bottom value="1uF (16V)"
C66 "10nF" 0603C#1 57.023,36.576 r0 bottom
C67 "100nF" 0402C#1 44.069,36.576 r90 bottom
C68 "100nF" 0402C#1 41.402,36.576 r90 bottom
C69 "100nF" 0402C#1 38.735,36.576 r90 bottom
C70 "100nF" 0402C#1 36.449,36.576 r90 bottom
C71 "100nF" 0402C#1 34.036,36.576 r90 bottom
C72 "100nF" 0402C#1 31.369,36.576 r90 bottom
C73 "100nF" 0402C#1 30.353,36.576 r90 bottom
C74 "100nF" 0402C#1 28.829,36.576 r90 bottom
C75 "100nF" 0402C#1 20.574,36.576 r270 bottom
C76 "2.2uF" 1206C#2 47.117,35.814 r90 bottom
C77 "100nF" 0402C#1 25.4,35.179 r0 bottom
C78 "100nF" 0402C#1 25.4,33.655 r0 bottom
C79 "4.7uF/50V" 1206C#2 56.642,32.385 r0 bottom value=4.7uF
C80 "1uF" CPOL_TAJ-A_1206_H180 25.4,31.623 r180 bottom value="1uF (16V)"
C81 "2.2uF" 1206C#2 47.117,30.861 r90 bottom
C82 "4.7uF 16V" CPOL_TAJ-A_1206_H180 54.102,28.067 r0 bottom
C83 "8.2pF" 0603C#1 23.368,27.813 r0 bottom
C84 "100nF" 0402C#2 26.797,26.543 r0 bottom
C85 "8.2pF" 0603C#2 23.368,26.289 r0 bottom
C86 "1uF" CPOL_TAJ-A_1206_H180 46.98,25.695 r270 bottom value="1uF (16V)"
C87 "100nF" 0402C#1 49.022,25.4 r90 bottom
C88 "100nF" 0402C#2 26.797,25.273 r0 bottom
C89 "100nF" 0402C#2 26.797,24.003 r0 bottom
C90 "100nF" 0402C#2 26.797,22.733 r0 bottom
C91 "100nF" 0402C#2 26.797,21.59 r0 bottom
C92 "100nF" 0402C#2 26.797,20.32 r0 bottom
C93 "3.0pF" 0603C#2 20.955,19.304 r270 bottom
C94 "3.0pF" 0603C#2 20.955,22.352 r90 bottom
C95 "100nF" 0402C#2 26.797,19.054 r0 bottom
C96 "2.2uF" 1206C#2 46.228,18.161 r270 bottom
C97 "100nF" 0402C#1 49.911,17.653 r0 bottom value=100NF
C98 "4.7uF" CPOL_TAJ-A_1206_H180 26.924,15.875 r270 bottom value="4.7uF 16V"
C101 "4.7uF 16V" CPOL_TAJ-A_1206_H180 16.891,8.763 r90 bottom
CN1 "USB-MINI-typeB" MINIUSB_AB_5SM_RA 31.267,123.045 r0 bottom
CN2 "FH19C-6S-05SH" FH19C-6S-0R5SH_FPC_CPT 55.095,103.695 r90 bottom
CN3 "PJ3028B-3" PJ3028B 8.719,102.108 r0 bottom
CN4 "[N/A]" HDR_2X3-1_2R54-6 34.109,86.106 r0 bottom
CN5 "SSW-110-22-X-S-VS" SSW-110-22-X-S-VS 5.842,83.185 r90 bottom
CN6 "SSW-108-22-X-S-VS" SSW-108-22-X-S-VS 54.102,76.581 r270 bottom
CN7 "SSW-108-22-X-S-VS" SSW-108-22-X-S-VS 5.842,58.801 r90 bottom
CN8 "SAMTEC SSW-106-22-x-S-VS" SSW-106-22-X-S-VS 54.102,56.261 r270 bottom
CN9 "PJS008-2003-1" MSD_PJS008_ 8.001,35.242 r90 bottom
CN10 "FH26-25S-0.3SHW" FPC25_FPC03025-1420 53.663,21.72 r270 bottom
CN11 "F206A-2*04MGF-A" SSM-104-L-DH 7.62,19.04 r270 bottom
CN12 "TSM-108-01-X-DV" TSM-108-01-X-DV 38.608,5.588 r0 bottom
CN13 "475900001" MOLEX_47590001 21.717,1.975 r0 bottom
D1 "BAT60JFILM" SOD-323 32.106,114.681 r270 bottom
D2 "BAT60JFILM" SOD-323 47.727,87.503 r270 bottom
D3 "BAT60JFILM" SOD-323 45.695,87.503 r270 bottom
D4 "BAT60JFILM" SOD-323 43.663,87.503 r270 bottom
D5 "EMIF02-USB03F2" BGA11_0R5_1R57X2R07 21.895,7.239 r90 bottom
H1 "POSITION HOLE" HOLE_C5R5D3 4.191,122.809 r0 top
H2 "POSITION HOLE" HOLE_C5R5D3 55.809,122.809 r0 top
H3 "POSITION HOLE" HOLE_C5R5D3 4.191,4.191 r0 top
H4 "POSITION HOLE" HOLE_C5R5D3 55.809,4.191 r0 top
HW3 "STICKER_BOARD_CPN" STICKER_BOARD-CPN_13X3 41.87,79.07 r180 bottom
HW4 "STICKER_QR_CODE" STICKER_QR_CODE_8X8 38.82,42.67 r180 bottom
JP1 "TSM-102-01-X-SV" TSM-102-01-X-SV#1 10.541,122.301 r0 bottom
JP2 "TSM-103-01-X-DV" TSM-103-01-X-DV 44.704,122.174 r270 bottom
JP5 "TSM-102-01-X-SV" TSM-102-01-X-SV#2 11.811,3.683 r270 bottom
L1 "BEAD(FCM1608KF-601T03)" 0603L 48.514,53.213 r270 bottom value=100uH
L2 "BEAD(FCM1608KF-601T03)" 0603L 46.736,53.213 r270 bottom value=100uH
L3 "BEAD" 0603L 51.308,47.498 r270 bottom value=100uH
L4 "4.7uH(1A)" 1210L 51.054,40.132 r270 bottom value=4.7uH
L5 "BEAD(FCM1608KF-601T03)" 0603L 21.971,36.83 r270 bottom value=100uH
LD1 "Green" 0603D 17.272,124.206 r270 top
LD2 "Orange" 0603D 21.971,124.206 r270 top
LD3 "Red" 0603D 26.67,124.206 r270 top
LD4 "Blue" 0603D 31.369,124.206 r270 top
LD5 "red" 0603D 46.101,117.475 r0 bottom
LD6 "67-22sursygc-s530-a2-tr8" LED2_3528 56.805,112.267 r0 bottom
LD7 "Green" 0603D 11.43,78.613 r0 bottom
LD8 "Green" 0603D 24.892,7.747 r270 top
LD9 "Red" 0603D 9.271,7.112 r0 bottom
R1 "10K" 0603R#1 10.033,121.031 r0 top value=10k
R2 "510" 0603R#1 17.272,120.904 r90 top
R3 "680" 0603R#1 21.971,120.904 r90 top
R4 "680" 0603R#1 26.67,120.904 r90 top
R5 "680" 0603R#1 31.369,120.904 r90 top
R6 "100K" 0603R#1 16.51,117.602 r90 bottom
R7 "820" 0603R#2 43.053,117.475 r0 bottom
R8 "100K" 0603R#1 38.735,117.475 r0 bottom
R9 "10K" 0402R#1 26.797,116.84 r0 bottom
R10 "100" 0603R#2 18.669,115.443 r0 bottom
R11 "100" 0603R#1 56.769,115.316 r0 bottom
R12 "1K5" 0603R#1 30.226,114.681 r270 bottom
R13 "0" 0603R#1 28.956,114.681 r270 bottom
R14 "0" 0603R#1 27.686,114.681 r270 bottom
R15 "100" 0603R#1 26.289,114.681 r270 bottom
R16 "36K" 0603R#1 24.892,114.681 r90 bottom
R17 "100" 0603R#1 54.229,114.554 r270 bottom
R18 "330" 0603R#1 16.129,113.03 r270 bottom
R19 "220K" 0603R#1 14.478,113.03 r270 bottom value=220k
R20 "100" 0603R#2 19.558,109.601 r0 bottom
R21 "0" 0603R#1 54.229,111.506 r270 bottom
R22 "2K7" 0603R#1 32.131,111.506 r270 bottom
R23 "0" 0603R#1 6.858,108.458 r0 bottom
R24 "0" 0603R#1 3.302,108.458 r0 bottom
R25 "4K7" 0603R#1 32.258,107.696 r90 bottom
R26 "100K" 0603R#1 19.177,105.664 r0 bottom
R27 "100K" 0603R#1 32.258,104.648 r270 bottom
R28 "10K" 0402R#1 30.48,97.536 r90 bottom
R29 "[N/A]" 0603R#1 29.21,97.536 r90 bottom value=10K
R30 "100K" 0603R#1 22.479,97.536 r270 bottom
R31 "[N/A]" 0603R#1 21.209,97.536 r90 bottom value=10K
R32 "4K7" 0603R#1 19.939,97.536 r90 bottom
R33 "4K7" 0603R#1 18.669,97.536 r90 bottom
R34 "100K" 0402R#1 56.642,96.901 r90 bottom
R35 "100" 0603R#1 23.876,111.633 r90 bottom
R36 "4K7" 0603R#1 53.594,96.901 r90 bottom value=4k7
R37 "2K7" 0603R#1 49.53,95.758 r0 bottom
R38 "10K" 0402R#1 39.37,93.98 r90 bottom
R39 "51" 0402R#1 15.748,93.853 r90 bottom
R40 "51" 0402R#1 14.351,93.853 r90 bottom
R41 "0" 0603R#1 10.287,91.44 r270 bottom
R42 "100K" 0603R#1 43.942,90.424 r0 bottom
R43 "[N/A]" 0603R#1 10.033,12.497 r270 bottom value=1K
R46 "0" 0603R#1 20.955,80.01 r270 bottom
R47 "47K" 0603R#1 19.558,80.01 r270 bottom
R48 "47K" 0603R#1 18.161,80.01 r90 bottom
R49 "510" 0603R#2 11.43,80.01 r0 bottom
R55 "10K" 0402R#2 9.144,46.355 r0 bottom
R57 "0" 0603R#2 5.715,44.958 r0 bottom
R58 "10" 0603R#1 56.388,44.196 r270 bottom
R59 "100K" 0603R#1 54.356,44.196 r90 bottom
R86 "47K" 0603R#2 18.034,41.148 r0 bottom
R87 "0" 0603R#1 47.498,40.132 r90 bottom
R114 "47K" 0603R#2 18.034,39.751 r0 bottom
R115 "47K" 0603R#2 18.034,38.227 r0 bottom
R116 "47K" 0603R#2 18.034,36.83 r0 bottom
R117 "0" 0603R#1 54.737,35.814 r270 bottom
R118 "4K7" 0603R#1 53.213,35.814 r270 bottom
R119 "[N/A]" 0603R#1 51.689,35.814 r270 bottom value=1K
R120 "47K" 0603R#2 18.034,35.56 r0 bottom
R121 "2K2" 0603R#1 18.034,34.163 r0 bottom
R122 "10K" 0402R#1 20.701,33.782 r270 bottom
R123 "0" 0603R#1 21.971,33.655 r270 bottom
R124 "2K2" 0603R#1 18.034,32.893 r0 bottom value=2k2
R131 "0" 0603R#2 23.368,24.892 r0 bottom
R132 "0" 0603R#1 23.368,20.066 r0 bottom
R133 "0" 0603R#1 23.368,21.59 r0 bottom
R135 "0" 0603R#1 42.418,17.018 r270 bottom
R140 "1K5" 0603R#1 36.068,17.018 r90 bottom
R142 "1K5" 0603R#1 33.782,17.018 r90 bottom
R143 "510" 0603R#1 31.115,17.018 r270 bottom
R144 "[N/A]" 0603R#1 29.591,17.018 r270 bottom value=1K
R149 "10K" 0402R#1 29.718,13.843 r270 bottom
R150 "[N/A]" 0603R#1 31.115,13.716 r270 bottom value=1K
R151 "0" 0603R#1 11.557,12.497 r90 bottom
R152 "10K" 0402R#1 13.081,12.192 r270 bottom
R153 "330" 0603R#1 27.686,11.938 r270 bottom
R154 "10K" 0603R#1 20.828,11.938 r270 bottom
R155 "47K" 0603R#1 19.304,11.938 r270 bottom
R156 "0" 0603R#1 11.557,9.398 r270 bottom
R157 "47K" 0603R#1 10.033,9.398 r270 bottom
R158 "680" 0603R#1 8.509,9.398 r90 bottom
R159 "0" 0603R#2 22.86,9.017 r0 bottom
R160 "0" 0603R#1 19.939,9.017 r0 bottom
R161 "0" 0603R#1 24.892,6.985 r270 bottom
SB1 "Closed by default" SB_0603 18.796,118.364 r0 bottom
SB2 "Closed by default" SB_0603 18.796,116.84 r180 bottom
SB3 "Closed by default" SB_0603 25.781,111.633 r270 bottom
SB4 "Open by default" SB_0603 23.749,97.536 r270 bottom
SB5 "Closed by default" SB_0603 11.43,81.407 r0 bottom
SB6 "Closed by default" SB_0603 38.989,17.018 r90 bottom
SB7 "Open by default" SB_0603 38.989,13.97 r270 bottom
SB8 "Closed by default" SB_0603 16.637,64.516 r0 bottom
SB9 "Open by default" SB_0603 48.133,61.214 r180 bottom
SB10 "Closed by default" SB_0603 48.133,59.563 r180 bottom
SB11 "Open by default" SB_0603 48.133,57.912 r180 bottom
SB12 "Closed by default" SB_0603 48.133,56.388 r180 bottom
SB13 "Open by default" SB_0603 50.038,53.213 r90 bottom
SB14 "Closed by default" SB_0603 49.149,28.194 r270 bottom
SB15 "Closed by default" SB_0603 32.512,17.018 r90 bottom
SB16 "Open by default" SB_0603 30.861,111.506 r90 bottom
SB17 "opened by default" SB_0603 9.144,124.841 r0 top
SB18 "Closed by default" SB_0603 45.339,5.842 r270 top
SB19 "Open by default" SB_0603 23.368,18.542 r180 bottom
T1 "9013" SOT-23 22.225,114.935 r270 bottom
T3 "9013" SOT-23 23.495,12.065 r90 bottom
TP1 "TP" TP_C40 33.02,39.878 r270 bottom
TP2 "TP" TP_C40 19.939,43.18 r270 bottom
TP3 "TP" TP_C40 30.988,39.878 r270 bottom
TP4 "TP" TP_C40 26.924,59.69 r270 bottom
TP5 "TP" TP_C40 20.955,48.514 r270 bottom
TP6 "TP" TP_C40 20.955,50.546 r270 bottom
TP7 "TP" TP_C40 8.763,48.006 r270 bottom
U1 "IMP34DT05TR" MIC_HCLGA_3X4X1_4LD_ 12.827,123.596 r270 top
U2 "IMP34DT05TR" MIC_HCLGA_3X4X1_4LD_ 28.83,5.615 r270 top
U3 "STLINK V2-1" LQFP48_0R5_9X9 26.162,104.902 r90 bottom
U4 "ST890CDR" SOIC8_1R27_4R9X6 43.942,93.853 r90 bottom
U5 "CS43L22" QFN40_0R5_6X6 16.129,85.598 r0 bottom
U6 "IMP34DT05TR" MIC_HCLGA_3X4X1_4LD_ 49.831,5.613 r270 top
U7 "LD1117S33TR" SOT-223 27.051,74.295 r0 bottom
U8 "LD1117S18TR" SOT-223 13.716,70.485 r270 bottom
U9 "LD3985M33R" SOT23-5#1 35.814,69.088 r0 bottom
U10 "LD1117S50TR" SOT-223 42.291,66.802 r270 bottom
U11 "ISSI IS42S32400F-6BL" ICC_VFBGA90_8X13_P080 36.195,55.626 r90 bottom value=IS42S32400F-6BL
U12 "MICRON MT25QL128ABA1EW9-0SIT" ICC_W-PDFN-8_8X6_P127 15.125,48.255 r0 bottom value=MT25QL128ABA1EW9-0SIT
U13 "STLD40DPUR" SON8_0R65_3X3 55.118,40.259 r0 bottom
U14 "STM32F469NIH6" BGA216_0R8_13X13 36.449,27.051 r0 bottom
U16 "STMPS2151STR" SOT23-5#2 13.97,8.763 r0 bottom
X1 "NX3225GD-8.00M" XTAL_2SM_3R2X2R5_H1#1 27.686,93.98 r0 bottom
X2 "NX3225GD-8.00M" XTAL_2SM_3R2X2R5_H1#2 18.288,26.035 r270 bottom
X3 "NX3215SA-32.768K" XTAL_2SM_3R2X1R5 18.567,20.968 r90 bottom
Z1 "STPS1L40M" DO-216AA 51.498,32.385 r0 bottom

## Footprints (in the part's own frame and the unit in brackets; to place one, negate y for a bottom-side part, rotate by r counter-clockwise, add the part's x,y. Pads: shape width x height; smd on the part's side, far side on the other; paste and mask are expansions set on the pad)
0402C#1 [mil] "0402C"
  rect 22x22 smd: 1(-20,0) 2(20,0)
  silkscreen extent -40,-20 40,20, body extent -35,-14 35,14, height 150
0402C#2 [mil] "0402C"
  rect 22x22 smd: 1(20,0) 2(-20,0)
  silkscreen extent -40,-20 40,20, body extent -35,-14 35,14, height 150
0402R#1 [mil] "0402R"
  rect 22x22 smd: 1(-20,0) 2(20,0)
  silkscreen extent -40,-20 40,20, body extent -35,-14 35,14, height 150
0402R#2 [mil] "0402R"
  rect 22x22 smd: 1(20,0) 2(-20,0)
  silkscreen extent -40,-20 40,20, body extent -35,-14 35,14, height 150
0603C#1 [mil] "0603C"
  rect 35x32 smd: 1(30,0) 2(-30,0)
  TOP keep-out region: 5,10 -5,10 -5,-10 5,-10 5,10
  silkscreen extent -57,-25 57,25, body extent -50,-20 50,20, height 150
0603C#2 [mil] "0603C"
  rect 35x32 smd: 1(-30,0) 2(30,0)
  TOP keep-out region: -5,-10 5,-10 5,10 -5,10 -5,-10
  silkscreen extent -57,-25 57,25, body extent -50,-20 50,20, height 150
0603D [mil] "0603D"
  rect 35x32 smd: 1(-30,0) 2(30,0)
  TOP keep-out region: -5,-10 5,-10 5,10 -5,10 -5,-10
  silkscreen extent -57,-25 65,25, body extent -50,-20 50,20, height 150
0603L [mil] "0603L"
  rect 35x32 smd: 1(-30,0) 2(30,0)
  silkscreen extent -60,-28 60,28, body extent -50,-19 50,19, height 150
0603R#1 [mil] "0603R"
  rect 31x32 smd: 1(-30,0) 2(30,0)
  TOP keep-out region: -5,10 -5,-10 5,-10 5,10 -5,10
  silkscreen extent -57,-25 57,25
0603R#2 [mil] "0603R"
  rect 31x32 smd: 1(30,0) 2(-30,0)
  TOP keep-out region: 5,-10 5,10 -5,10 -5,-10 5,-10
  silkscreen extent -57,-25 57,25, body extent -50,-20 50,20, height 150
1206C#1 [mil] "1206C"
  rect 46x60 smd: 1(58,0) 2(-58,0)
  silkscreen extent -91,-40 91,40, body extent -81,-30 81,30, height 150
1206C#2 [mil] "1206C"
  rect 46x60 smd: 1(-58,0) 2(58,0)
  silkscreen extent -91,-40 91,40, body extent -81,-30 81,30, height 150
1210L [mil] "1210L"
  rect 46x100 smd: 1(-58,0) 2(58,0)
  silkscreen extent -91,-60 91,60, body extent -83,-53 83,53, height 150
BGA11_0R5_1R57X2R07 [mm] "BGA11_0R5_1R57X2R07"
  round 0.249 smd: A2(0,0.75) A3(0.5,0.75) B1(-0.5,0.25) B2(0,0.25) B3(0.5,0.25) C1(-0.5,-0.25) C2(0,-0.25) C3(0.5,-0.25) D1(-0.5,-0.75) D2(0,-0.75) D3(0.5,-0.75)
  silkscreen extent -0.79,-1.04 0.79,1.04
BGA216_0R8_13X13 [mil] "BGA216_0R8_13X13"
  round 16 smd: A1(-220.47,220.47) A2(-188.98,220.47) A3(-157.48,220.47) A4(-125.98,220.47) A5(-94.49,220.47) A6(-62.99,220.47) A7(-31.5,220.47) A8(0,220.47) A9(31.5,220.47) A10(62.99,220.47) A11(94.49,220.47) A12(125.98,220.47) A13(157.48,220.47) A14(188.98,220.47) A15(220.47,220.47) B1(-220.47,188.98) B2(-188.98,188.98) B3(-157.48,188.98) B4(-125.98,188.98) B5(-94.49,188.98) B6(-62.99,188.98) B7(-31.5,188.98) B8(0,188.98) B9(31.5,188.98) B10(62.99,188.98) B11(94.49,188.98) B12(125.98,188.98) B13(157.48,188.98) B14(188.98,188.98) B15(220.47,188.98) C1(-220.47,157.48) C2(-188.98,157.48) C3(-157.48,157.48) C4(-125.98,157.48) C5(-94.49,157.48) C6(-62.99,157.48) C7(-31.5,157.48) C8(0,157.48) C9(31.5,157.48) C10(62.99,157.48) C11(94.49,157.48) C12(125.98,157.48) C13(157.48,157.48) C14(188.98,157.48) C15(220.47,157.48) D1(-220.47,125.98) D2(-188.98,125.98) D3(-157.48,125.98) D4(-125.98,125.98) D5(-94.49,125.98) D6(-62.99,125.98) D7(-31.5,125.98) D8(0,125.98) D9(31.5,125.98) D10(62.99,125.98) D11(94.49,125.98) D12(125.98,125.98) D13(157.48,125.98) D14(188.98,125.98) D15(220.47,125.98) E1(-220.47,94.49) E2(-188.98,94.49) E3(-157.48,94.49) E4(-125.98,94.49) E5(-94.49,94.49) E6(-62.99,94.49) E7(-31.5,94.49) E8(0,94.49) E9(31.5,94.49) E10(62.99,94.49) E11(94.49,94.49) E12(125.98,94.49) E13(157.48,94.49) E14(188.98,94.49) E15(220.47,94.49) F1(-220.47,62.99) F2(-188.98,62.99) F3(-157.48,62.99) F4(-125.98,62.99) F5(-94.49,62.99) F6(-62.99,62.99) F7(-31.5,62.99) F8(0,62.99) F9(31.5,62.99) F10(62.99,62.99) F11(94.49,62.99) F12(125.98,62.99) F13(157.48,62.99) F14(188.98,62.99) F15(220.47,62.99) G1(-220.47,31.5) G2(-188.98,31.5) G3(-157.48,31.5) G4(-125.98,31.5) G5(-94.49,31.5) G6(-62.99,31.5) G10(62.99,31.5) G11(94.49,31.5) G12(125.98,31.5) G13(157.48,31.5) G14(188.98,31.5) G15(220.47,31.5) H1(-220.47,0) H2(-188.98,0) H3(-157.48,0) H4(-125.98,0) H5(-94.49,0) H6(-62.99,0) H10(62.99,0) H11(94.49,0) H12(125.98,0) H13(157.48,0) H14(188.98,0) H15(220.47,0) J1(-220.47,-31.5) J2(-188.98,-31.5) J3(-157.48,-31.5) J4(-125.98,-31.5) J5(-94.49,-31.5) J6(-62.99,-31.5) J10(62.99,-31.5) J11(94.49,-31.5) J12(125.98,-31.5) J13(157.48,-31.5) J14(188.98,-31.5) J15(220.47,-31.5) K1(-220.47,-62.99) K2(-188.98,-62.99) K3(-157.48,-62.99) K4(-125.98,-62.99) K5(-94.49,-62.99) K6(-62.99,-62.99) K7(-31.5,-62.99) K8(0,-62.99) K9(31.5,-62.99) K10(62.99,-62.99) K11(94.49,-62.99) K12(125.98,-62.99) K13(157.48,-62.99) K14(188.98,-62.99) K15(220.47,-62.99) L1(-220.47,-94.49) L2(-188.98,-94.49) L3(-157.48,-94.49) L4(-125.98,-94.49) L5(-94.49,-94.49) L6(-62.99,-94.49) L7(-31.5,-94.49) L8(0,-94.49) L9(31.5,-94.49) L10(62.99,-94.49) L11(94.49,-94.49) L12(125.98,-94.49) L13(157.48,-94.49) L14(188.98,-94.49) L15(220.47,-94.49) M1(-220.47,-125.98) M2(-188.98,-125.98) M3(-157.48,-125.98) M4(-125.98,-125.98) M5(-94.49,-125.98) M6(-62.99,-125.98) M7(-31.5,-125.98) M8(0,-125.98) M9(31.5,-125.98) M10(62.99,-125.98) M11(94.49,-125.98) M12(125.98,-125.98) M13(157.48,-125.98) M14(188.98,-125.98) M15(220.47,-125.98) N1(-220.47,-157.48) N2(-188.98,-157.48) N3(-157.48,-157.48) N4(-125.98,-157.48) N5(-94.49,-157.48) N6(-62.99,-157.48) N7(-31.5,-157.48) N8(0,-157.48) N9(31.5,-157.48) N10(62.99,-157.48) N11(94.49,-157.48) N12(125.98,-157.48) N13(157.48,-157.48) N14(188.98,-157.48) N15(220.47,-157.48) P1(-220.47,-188.98) P2(-188.98,-188.98) P3(-157.48,-188.98) P4(-125.98,-188.98) P5(-94.49,-188.98) P6(-62.99,-188.98) P7(-31.5,-188.98) P8(0,-188.98) P9(31.5,-188.98) P10(62.99,-188.98) P11(94.49,-188.98) P12(125.98,-188.98) P13(157.48,-188.98) P14(188.98,-188.98) P15(220.47,-188.98) R1(-220.47,-220.47) R2(-188.98,-220.47) R3(-157.48,-220.47) R4(-125.98,-220.47) R5(-94.49,-220.47) R6(-62.99,-220.47) R7(-31.5,-220.47) R8(0,-220.47) R9(31.5,-220.47) R10(62.99,-220.47) R11(94.49,-220.47) R12(125.98,-220.47) R13(157.48,-220.47) R14(188.98,-220.47) R15(220.47,-220.47)
  silkscreen extent -335,-335 335,335, body extent -256,-256 256,256, height 150
CPOL_TAJ-A_1206_H180 [mm] "TAN-A"
  rect 1.45x1.6 smd mask+0.05: 1(-1.175,0) 2(1.175,0)
  silkscreen extent -2.15,-1.05 1.7,1.05, body extent -1.7,-0.9 1.7,0.9, height 1.8
CPOL_TAJ-B_1210_H210 [mm]
  rect 1.35x2.8 smd mask+0.05: 1(-1.375,0) 2(1.375,0)
  silkscreen extent -2.33,-1.68 1.85,1.68, body extent -1.85,-1.5 1.85,1.5, height 2.11
DO-216AA [mil] "DO-216AA"
  rect 45x32 smd: 1(-67.5,0)
  rect 90x89 smd: 2(22.5,0)
  silkscreen extent -102,-55 102,55, body extent -106,-58 106,58, height 150
FH19C-6S-0R5SH_FPC_CPT [mil] "FH19C-6S-0R5SH_FPC_CPT"
  rect 11x49 smd: 1(51.71,100) 2(32.03,100) 3(12.34,100) 4(-7.34,100) 5(-27.03,100) 6(-46.71,100)
  rect 86x79 smd: 7(-117.58,-7.28) 8(122.58,-7.28)
  silkscreen extent -143,-131 148,164, body extent -168,-130 168,130, height 150
FPC25_FPC03025-1420 [mil] "FPC25_FPC03025-1420"
  rect 12x32 smd: 1(-141.61,-55.59) 2(-129.8,58.59) 3(-117.99,-55.59) 4(-106.18,58.59) 5(-94.37,-55.59) 6(-82.56,58.59) 7(-70.75,-55.59) 8(-58.94,58.59) 9(-47.12,-55.59) 10(-35.31,58.59) 11(-23.5,-55.59) 12(-11.69,58.59) 13(0.12,-55.59) 14(11.93,58.59) 15(23.74,-55.59) 16(35.55,58.59) 17(47.36,-55.59) 18(59.18,58.59) 19(70.99,-55.59) 20(82.8,58.59) 21(94.61,-55.59) 22(106.42,58.59) 23(118.23,-55.59) 24(130.04,58.59) 25(141.85,-55.59)
  rect 16x44 smd: ""(-169.17,-41.81) ""(169.41,-41.81)
  silkscreen extent -182,-121 182,69, body extent -177,-78 177,78, height 150
HDR_2X3-1_2R54-6 [mil] "HDR_2X3-1_2R54-6"
  rect 60x60 / inner round 60 / far side rect 60x60 hole 40: 1(-102.89,-50)
  round 60 hole 40: 2(-102.89,50) 3(-2.89,-50) 4(-2.89,50) 5(97.11,-50)
  silkscreen extent -152,-105 148,105, body extent -148,-100 148,100, height 150
HOLE_C5R5D3 [mil] "HOLE_C5R5D3"
  round 217 / inner round 148 / far side round 217 hole 118: 1(0,0)
  body extent -113,-113 113,113, height 150
ICC_VFBGA90_8X13_P080 [mm] "B5__Pb Free"
  round 0.4 smd mask+0.05: A1(-3.2,5.6) A2(-2.4,5.6) A3(-1.6,5.6) A7(1.6,5.6) A8(2.4,5.6) A9(3.2,5.6) B1(-3.2,4.8) B2(-2.4,4.8) B3(-1.6,4.8) B7(1.6,4.8) B8(2.4,4.8) B9(3.2,4.8) C1(-3.2,4) C2(-2.4,4) C3(-1.6,4) C7(1.6,4) C8(2.4,4) C9(3.2,4) D1(-3.2,3.2) D2(-2.4,3.2) D3(-1.6,3.2) D7(1.6,3.2) D8(2.4,3.2) D9(3.2,3.2) E1(-3.2,2.4) E2(-2.4,2.4) E3(-1.6,2.4) E7(1.6,2.4) E8(2.4,2.4) E9(3.2,2.4) F1(-3.2,1.6) F2(-2.4,1.6) F3(-1.6,1.6) F7(1.6,1.6) F8(2.4,1.6) F9(3.2,1.6) G1(-3.2,0.8) G2(-2.4,0.8) G3(-1.6,0.8) G7(1.6,0.8) G8(2.4,0.8) G9(3.2,0.8) H1(-3.2,0) H2(-2.4,0) H3(-1.6,0) H7(1.6,0) H8(2.4,0) H9(3.2,0) J1(-3.2,-0.8) J2(-2.4,-0.8) J3(-1.6,-0.8) J7(1.6,-0.8) J8(2.4,-0.8) J9(3.2,-0.8) K1(-3.2,-1.6) K2(-2.4,-1.6) K3(-1.6,-1.6) K7(1.6,-1.6) K8(2.4,-1.6) K9(3.2,-1.6) L1(-3.2,-2.4) L2(-2.4,-2.4) L3(-1.6,-2.4) L7(1.6,-2.4) L8(2.4,-2.4) L9(3.2,-2.4) M1(-3.2,-3.2) M2(-2.4,-3.2) M3(-1.6,-3.2) M7(1.6,-3.2) M8(2.4,-3.2) M9(3.2,-3.2) N1(-3.2,-4) N2(-2.4,-4) N3(-1.6,-4) N7(1.6,-4) N8(2.4,-4) N9(3.2,-4) P1(-3.2,-4.8) P2(-2.4,-4.8) P3(-1.6,-4.8) P7(1.6,-4.8) P8(2.4,-4.8) P9(3.2,-4.8) R1(-3.2,-5.6) R2(-2.4,-5.6) R3(-1.6,-5.6) R7(1.6,-5.6) R8(2.4,-5.6) R9(3.2,-5.6)
  silkscreen extent -4.2,-6.55 4.05,6.7, body extent -4.05,-6.55 4.05,6.55, height 1.1
ICC_W-PDFN-8_8X6_P127 [mm]
  rect 1.35x0.8 smd mask+0.05: 1(-3.575,1.905) 2(-3.575,0.635) 3(-3.575,-0.635) 4(-3.575,-1.905) 5(3.575,-1.905) 6(3.575,-0.635) 7(3.575,0.635) 8(3.575,1.905)
  rect 4x5 smd mask+0.05: 9(0,0)
  silkscreen extent -4.47,-3 4,3, body extent -4,-3 4,3, height 0.81
LED2_3528 [mil] "LED2_3528"
  rect 44x59 smd: 1(29.53,59.06) 2(29.53,-59.06) 3(-29.53,-59.06) 4(-29.53,59.06)
  silkscreen extent -65,-69 109,69, body extent -55,-90 55,90, height 150
LQFP48_0R5_9X9 [mil] "LQFP48_0R5_9X9"
  rect 53x11 smd: 1(-171.26,108.27) 2(-171.26,88.58) 3(-171.26,68.9) 4(-171.26,49.21) 5(-171.26,29.53) 6(-171.26,9.84) 7(-171.26,-9.84) 8(-171.26,-29.53) 9(-171.26,-49.21) 10(-171.26,-68.9) 11(-171.26,-88.58) 12(-171.26,-108.27) 25(171.26,-108.27) 26(171.26,-88.58) 27(171.26,-68.9) 28(171.26,-49.21) 29(171.26,-29.53) 30(171.26,-9.84) 31(171.26,9.84) 32(171.26,29.53) 33(171.26,49.21) 34(171.26,68.9) 35(171.26,88.58) 36(171.26,108.27)
  rect 11x53 smd: 13(-108.27,-171.26) 14(-88.58,-171.26) 15(-68.9,-171.26) 16(-49.21,-171.26) 17(-29.53,-171.26) 18(-9.84,-171.26) 19(9.84,-171.26) 20(29.53,-171.26) 21(49.21,-171.26) 22(68.9,-171.26) 23(88.58,-171.26) 24(108.27,-171.26) 37(108.27,171.26) 38(88.58,171.26) 39(68.9,171.26) 40(49.21,171.26) 41(29.53,171.26) 42(9.84,171.26) 43(-9.84,171.26) 44(-29.53,171.26) 45(-49.21,171.26) 46(-68.9,171.26) 47(-88.58,171.26) 48(-108.27,171.26)
  silkscreen extent -226,-220 215,220
MIC_HCLGA_3X4X1_4LD_ [mm]
  rect 0.4x0.95 smd paste+0 mask+0.05: 1(0.45,-0.675) 2(0.45,0.675) 3(-0.45,0.675) 4(-0.45,-0.675)
  rect 0.35x2.3 smd paste+0 mask+0.05: 5(-1.225,0) 5(1.225,0)
  rect 1.3x0.35 smd paste+0 mask+0.05: 5(0,1.725) 5(0,-1.725)
  silkscreen extent -1.55,-2.05 1.55,2.05, body extent -1.45,-1.95 1.45,1.95, height 1.03
MINIUSB_AB_5SM_RA [mil] "MINIUSB_AB_5SM_RA"
  rect 20x89 smd: 1(-60.98,154.31) 2(-29.48,154.31) 3(2.01,154.31) 4(33.51,154.31) 5(65,154.31)
  rect 79x99 smd: 6(-165.31,142.5) 7(-165.31,-74.04) 8(169.33,-74.04) 9(169.33,142.5)
  round 39 hole 39 unplated: ""(-84.6,35.22) ""(88.63,35.22)
  Multi-Layer keep-out region: -48.86,35.22 -50.08,25.97 -53.65,17.35 -59.33,9.95 -66.73,4.27 -75.35,0.7 -84.6,-0.52 -93.85,0.7 -102.47,4.27 -102.47,4.27 -109.87,9.95 -115.55,17.35 -119.12,25.97 -120.34,35.22 -119.12,44.47 -115.55,53.09 -109.87,60.49 -102.47,66.17 -102.47,66.17 -93.85,69.74 -84.6,70.96 -75.35,69.74 -66.73,66.17 -59.33,60.49 -53.65,53.09 -50.08,44.47 -48.86,35.22
  Multi-Layer keep-out region: 124.37,35.22 123.15,25.97 119.58,17.35 113.9,9.95 106.5,4.27 97.88,0.7 88.63,-0.52 79.38,0.7 70.76,4.27 70.76,4.27 63.36,9.95 57.68,17.35 54.11,25.97 52.89,35.22 54.11,44.47 57.68,53.09 63.36,60.49 70.76,66.17 70.76,66.17 79.38,69.74 88.63,70.96 97.88,69.74 106.5,66.17 113.9,60.49 119.58,53.09 123.15,44.47 124.37,35.22
  silkscreen extent -155,-202 160,233, body extent -210,-198 210,198, height 150
MOLEX_47590001 [mil] "MOLEX_47590001"
  rect 16x53 smd: 1(-51.18,-85.06) 2(-25.59,-85.06) 3(0,-85.06) 4(25.59,-85.06) 5(51.18,-85.06)
  oval 42x63 hole 33 slot 30 at 0 deg: 6(-89.57,-97.86) 7(89.57,-97.86)
  oval 55x75 hole 59 slot 33 at 0 deg: 8(163.39,27.34) 9(-163.39,27.34)
  rect 114x79 smd: 10(0,20.25)
  silkscreen extent -161,-151 161,131, body extent -190,-130 190,130, height 150
MSD_PJS008_ [mil] "MSD_PJS008_"
  rect 32x63 smd: 1(-99.43,278.35) 2(-56.12,278.35) 3(-12.81,278.35) 4(30.49,278.35) 5(73.8,278.35) 6(117.11,278.35) 7(160.41,278.35) 8(203.72,278.35)
  rect 33x63 smd: 9(249,278.35)
  rect 77x75 smd: 10(284.43,-123.23)
  rect 60x121 smd: 11(293.29,-239.37)
  rect 55x135 smd: 12(-295.43,-239.65)
  rect 63x138 smd: 13(-291.36,193.7)
  rect 47x122 smd: 14(299.19,213.39)
  round 28 hole 28 unplated: ""(-157.5,50) ""(139.74,50)
  Multi-Layer keep-out region: -157.5,79.25 -149.93,78.25 -142.87,75.33 -136.82,70.68 -132.17,64.63 -129.25,57.57 -128.25,50 -129.25,42.43 -132.17,35.37 -132.17,35.37 -136.82,29.32 -142.87,24.67 -149.93,21.75 -157.5,20.75 -165.07,21.75 -172.13,24.67 -178.18,29.32 -182.83,35.37 -182.83,35.37 -185.75,42.43 -186.75,50 -185.75,57.57 -182.83,64.63 -178.18,70.68 -172.13,75.33 -165.07,78.25 -157.5,79.25
  Multi-Layer keep-out region: 139.74,79.25 147.31,78.25 154.37,75.33 160.42,70.68 165.07,64.63 167.99,57.57 168.99,50 167.99,42.43 165.07,35.37 165.07,35.37 160.42,29.32 154.37,24.67 147.31,21.75 139.74,20.75 132.17,21.75 125.11,24.67 119.06,29.32 114.41,35.37 114.41,35.37 111.49,42.43 110.49,50 111.49,57.57 114.41,64.63 119.06,70.68 125.11,75.33 132.17,78.25 139.74,79.25
  silkscreen extent -308,-315 292,312, body extent -328,-315 328,315, height 150
PB10 [mil] "PB10"
  rect 60x40 smd: 1(177.17,87.5) 2(177.17,-87.5) 3(-177.17,-87.5) 4(-177.17,87.5)
  silkscreen extent -125,-125 125,125, body extent -207,-108 207,108, height 150
PJ3028B [mil] "PJ3028B"
  rect 48x98 smd: 2(-301.79,-157.48) 7(-226.99,157.48)
  rect 79x98 smd: 3(-187.62,-157.48) 4(-116.75,157.48) 6(174.58,-157.48)
  rect 98x79 smd: 5(334.03,31.5)
  round 79 hole 79 unplated: ""(-148.25,0) ""(127.34,0)
  Multi-Layer keep-out region: -93.45,0 -95.32,-14.18 -100.79,-27.4 -109.5,-38.75 -120.85,-47.46 -134.07,-52.93 -148.25,-54.8 -162.43,-52.93 -175.65,-47.46 -175.65,-47.46 -187,-38.75 -195.71,-27.4 -201.18,-14.18 -203.05,0 -201.18,14.18 -195.71,27.4 -187,38.75 -175.65,47.46 -175.65,47.46 -162.43,52.93 -148.25,54.8 -134.07,52.93 -120.85,47.46 -109.5,38.75 -100.79,27.4 -95.32,14.18 -93.45,0
  Multi-Layer keep-out region: 182.14,0 180.27,-14.18 174.8,-27.4 166.09,-38.75 154.74,-47.46 141.52,-52.93 127.34,-54.8 113.16,-52.93 99.94,-47.46 99.94,-47.46 88.59,-38.75 79.88,-27.4 74.41,-14.18 72.54,0 74.41,14.18 79.88,27.4 88.59,38.75 99.94,47.46 99.94,47.46 113.16,52.93 127.34,54.8 141.52,52.93 154.74,47.46 166.09,38.75 174.8,27.4 180.27,14.18 182.14,0
  silkscreen extent -384,-118 285,118, body extent -383,-210 383,210, height 150
QFN40_0R5_6X6 [mil] "QFN40_0R5_6X6"
  oval 32x11 smd: 1(-116.14,88.58) 2(-116.14,68.9) 3(-116.14,49.21) 4(-116.14,29.53) 5(-116.14,9.84) 6(-116.14,-9.84) 7(-116.14,-29.53) 8(-116.14,-49.21) 9(-116.14,-68.9) 10(-116.14,-88.58) 21(116.14,-88.58) 22(116.14,-68.9) 23(116.14,-49.21) 24(116.14,-29.53) 25(116.14,-9.84) 26(116.14,9.84) 27(116.14,29.53) 28(116.14,49.21) 29(116.14,68.9) 30(116.14,88.58)
  oval 11x32 smd: 11(-88.58,-116.14) 12(-68.9,-116.14) 13(-49.21,-116.14) 14(-29.53,-116.14) 15(-9.84,-116.14) 16(9.84,-116.14) 17(29.53,-116.14) 18(49.21,-116.14) 19(68.9,-116.14) 20(88.58,-116.14) 31(88.58,116.14) 32(68.9,116.14) 33(49.21,116.14) 34(29.53,116.14) 35(9.84,116.14) 36(-9.84,116.14) 37(-29.53,116.14) 38(-49.21,116.14) 39(-68.9,116.14) 40(-88.58,116.14)
  rect 162x162 smd: 41(0,0)
  TOP keep-out region: -124.02,124.02 -100.79,124.02 -100.79,100.79 -124.02,100.79 -124.02,124.02
  TOP keep-out region: -124.02,-124.02 -124.02,-100.79 -100.79,-100.79 -100.79,-124.02 -124.02,-124.02
  TOP keep-out region: 124.02,-124.02 100.79,-124.02 100.79,-100.79 124.02,-100.79 124.02,-124.02
  TOP keep-out region: 124.02,124.02 124.02,100.79 100.79,100.79 100.79,124.02 124.02,124.02
  silkscreen extent -145,-145 150,150, body extent -133,-133 133,133, height 150
SB_0603 [mil] "SB_0603"
  round 6 smd: 1(30,0) 2(-30,0)
  TOP region: -50,-20 -50,20 -13.75,20 6.25,0 -13.75,-20 -50,-20
  TOP region: 50,20 -3.75,20 10.75,5.5 16.32,-0.08 -3.6,-20 50,-20 50,20
  silkscreen extent -57,-25 57,25, body extent -50,-20 50,20, height 150
SOD-323 [mil] "SOD-323"
  rect 32x32 smd: 1(-44.29,-1) 2(44.29,-1)
  silkscreen extent -90,-36 50,44, body extent -65,-26 65,26, height 150
SOIC8_1R27_4R9X6 [mil] "SOIC8_1R27_4R9X6"
  rect 22x70 smd: 1(-75,-103.3) 2(-25,-103.3) 3(25,-103.3) 4(75,-103.3) 5(75,103.3) 6(25,103.3) 7(-25,103.3) 8(-75,103.3)
  silkscreen extent -100,-172 100,55, body extent -96,-141 96,141, height 150
SON8_0R65_3X3 [mil] "SON8_0R65_3X3"
  rect 16x31 smd: 1(-38.39,-58.07) 2(-12.8,-58.07) 3(12.8,-58.07) 4(38.39,-58.07) 5(38.39,58.07) 6(12.8,58.07) 7(-12.8,58.07) 8(-38.39,58.07)
  oct 1x1 smd: 9(0,0)
  TOP region: -39.37,-31.5 39.37,-31.5 39.37,-20.67 74.8,-20.67 74.8,-4.92 39.37,-4.92 39.37,4.92 74.8,4.92 74.8,20.67 39.37,20.67 39.37,31.5 -39.37,31.5 -39.37,20.67 -74.8,20.67 -74.8,4.92 -39.37,4.92 -39.37,-4.92 -74.8,-4.92 -74.8,-20.67 -39.37,-20.67 -39.37,-31.5
  silkscreen extent -84,-110 65,65, body extent -78,-78 78,78, height 150
SOT23-5#1 [mil] "SOT23-5"
  rect 25x45 smd: 1(-37.4,-47.24) 2(0,-47.24) 3(37.4,-47.24) 4(37.4,47.24) 5(-37.4,47.24)
  silkscreen extent -89,-99 65,35, body extent -57,-70 57,70, height 150
SOT23-5#2 [mil] "SOT23-5"
  rect 25x45 smd: 1(37.4,47.24) 2(0,47.24) 3(-37.4,47.24) 4(-37.4,-47.24) 5(37.4,-47.24)
  silkscreen extent -65,-35 65,106, body extent -57,-70 57,70, height 150
SOT-23 [mil] "SOT-23"
  rect 25x45 smd: 1(-37.4,-43.31) 2(37.4,-43.31) 3(0,43.31)
  silkscreen extent -60,-35 60,35, body extent -60,-70 60,70, height 150
SOT-223 [mil] "SOT-223"
  rect 40x71 smd: 1(-90.55,-124.02) 2(0,-124.02) 3(90.55,-124.02)
  rect 130x71 smd: 4(0,124.02)
  silkscreen extent -130,-194 130,75, body extent -128,-160 128,160, height 150
SSM-104-L-DH [mil] "SSM-104-L-DH"
  rect 40x90 smd: 1(149.61,-184.96) 2(149.61,184.96) 3(49.61,-184.96) 4(49.61,184.96) 5(-50.39,-184.96) 6(-50.39,184.96) 7(-150.39,-184.96) 8(-150.39,184.96)
  round 47 hole 47 unplated: ""(-100.39,0) ""(99.61,0)
  Multi-Layer keep-out region: -100.39,-39.71 -110.67,-38.36 -120.24,-34.39 -128.47,-28.08 -134.78,-19.85 -138.75,-10.28 -140.1,0 -138.75,10.28 -134.78,19.85 -134.78,19.85 -128.47,28.08 -120.24,34.39 -110.67,38.36 -100.39,39.71 -90.11,38.36 -80.54,34.39 -72.31,28.08 -66,19.85 -66,19.85 -62.03,10.28 -60.68,0 -62.03,-10.28 -66,-19.85 -72.31,-28.08 -80.54,-34.39 -90.11,-38.36 -100.39,-39.71
  Multi-Layer keep-out region: 99.61,-39.71 89.33,-38.36 79.76,-34.39 71.53,-28.08 65.22,-19.85 61.25,-10.28 59.9,0 61.25,10.28 65.22,19.85 65.22,19.85 71.53,28.08 79.76,34.39 89.33,38.36 99.61,39.71 109.89,38.36 119.46,34.39 127.69,28.08 134,19.85 134,19.85 137.97,10.28 139.32,0 137.97,-10.28 134,-19.85 127.69,-28.08 119.46,-34.39 109.89,-38.36 99.61,-39.71
  silkscreen extent -200,-217 205,160, body extent -200,-235 200,235, height 150
SSW-106-22-X-S-VS [mil] "SSW-106-22-X-S-VS"
  rect 40x95 smd: 1(-250,-67.5) 2(-150,67.5) 3(-50,-67.5) 4(50,67.5) 5(150,-67.5) 6(250,67.5)
  silkscreen extent -310,-155 310,47, body extent -310,-120 310,120, height 150
SSW-108-22-X-S-VS [mil] "SSW-108-22-X-S-VS"
  rect 40x95 smd: 1(-350,-67.5) 2(-250,67.5) 3(-150,-67.5) 4(-50,67.5) 5(50,-67.5) 6(150,67.5) 7(250,-67.5) 8(350,67.5)
  silkscreen extent -410,-99 410,47, body extent -410,-120 410,120, height 150
SSW-110-22-X-S-VS [mil] "SSW-110-22-X-S-VS"
  rect 40x95 smd: 1(-450,-67.5) 2(-350,67.5) 3(-250,-67.5) 4(-150,67.5) 5(-50,-67.5) 6(50,67.5) 7(150,-67.5) 8(250,67.5) 9(350,-67.5) 10(450,67.5)
  silkscreen extent -510,-150 510,47, body extent -510,-120 510,120, height 150
STICKER_BOARD-CPN_13X3 [mm] "Sticker to mention board CPN code"
  silkscreen extent -6.5,-1.5 6.5,1.5, body extent -6.5,-1.5 6.5,1.5, height 0.01
STICKER_QR_CODE_8X8 [mm] "Sticker to mention board QR code 8X8"
  silkscreen extent -4,-4 4,4
TP_C40 [mil] "TP_C40"
  round 40 smd paste-50: 1(0,0)
  silkscreen extent -29,-29 29,29, body extent -31,-31 31,31, height 150
TSM-102-01-X-SV#1 [mm] "TSM-102-01-X-SV"
  rect 1.27x3.429 smd: 1(-1.27,1.46) 2(1.27,-1.46)
  silkscreen extent -2.54,-1.27 2.54,4.2, body extent -2.54,-3.3 2.54,3.3, height 3.81
TSM-102-01-X-SV#2 [mm] "TSM-102-01-X-SV"
  rect 1.27x3.429 smd: 1(1.27,-1.46) 2(-1.27,1.46)
  silkscreen extent -2.54,-4.2 2.54,1.27, body extent -2.54,-3.3 2.54,3.3, height 3.81
TSM-103-01-X-DV [mil] "TSM-103-01-X-DV"
  rect 50x145 smd: 1(-100,-97.44) 2(-100,97.44) 3(0,-97.44) 4(0,97.44) 5(100,-97.44) 6(100,97.44)
  silkscreen extent -164,-151 150,100, body extent -150,-175 150,175, height 150
TSM-108-01-X-DV [mil] "TSM-108-01-X-DV"
  rect 50x145 smd: 1(-350,-97.44) 2(-350,97.44) 3(-250,-97.44) 4(-250,97.44) 5(-150,-97.44) 6(-150,97.44) 7(-50,-97.44) 8(-50,97.44) 9(50,-97.44) 10(50,97.44) 11(150,-97.44) 12(150,97.44) 13(250,-97.44) 14(250,97.44) 15(350,-97.44) 16(350,97.44)
  silkscreen extent -400,-206 400,100, body extent -400,-175 400,175, height 150
XTAL_2SM_3R2X1R5 [mil] "XTAL_2SM_3R2X1R5"
  rect 51x63 smd: 1(-45.78,-1) 2(44.78,-1)
  silkscreen extent -86,-46 84,44, body extent -72,-31 72,31, height 150
XTAL_2SM_3R2X2R5_H1#1 [mil] "XTAL_2SM_3R2X2R5_H1"
  rect 71x106 smd: 1(45.28,0) 2(-45.28,0)
  silkscreen extent -95,-65 95,65, body extent -84,-56 84,56, height 150
XTAL_2SM_3R2X2R5_H1#2 [mil] "XTAL_2SM_3R2X2R5_H1"
  rect 71x106 smd: 1(-45.28,0) 2(45.28,0)
  silkscreen extent -95,-65 95,65, body extent -84,-56 84,56, height 150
